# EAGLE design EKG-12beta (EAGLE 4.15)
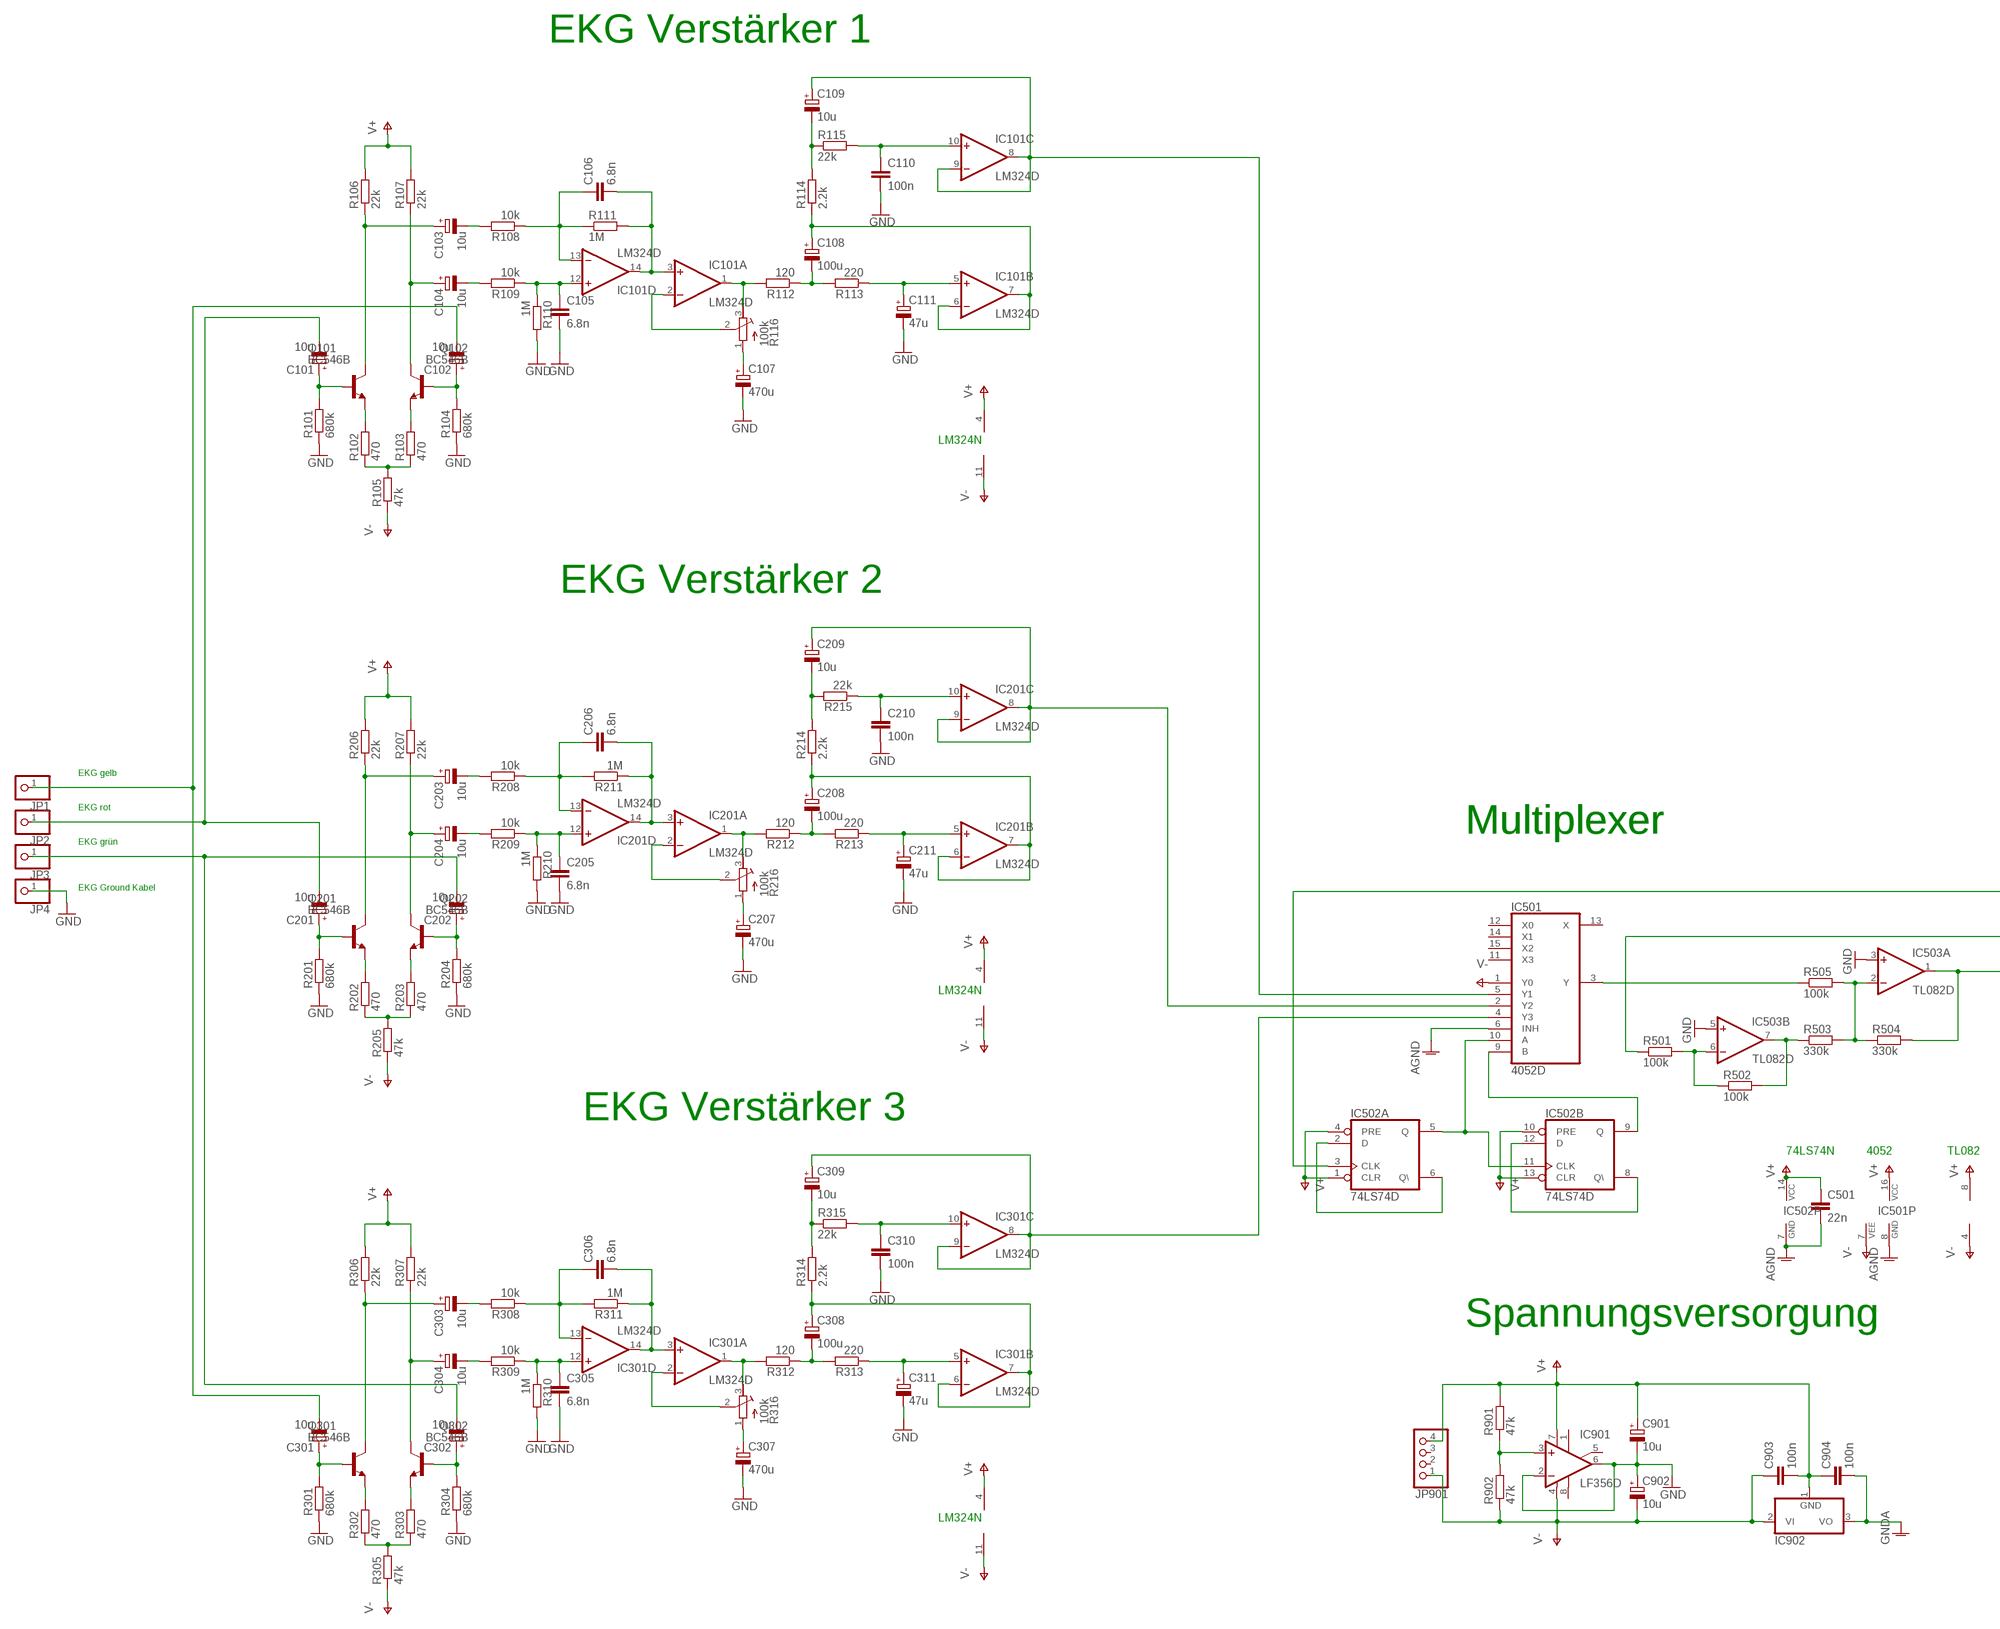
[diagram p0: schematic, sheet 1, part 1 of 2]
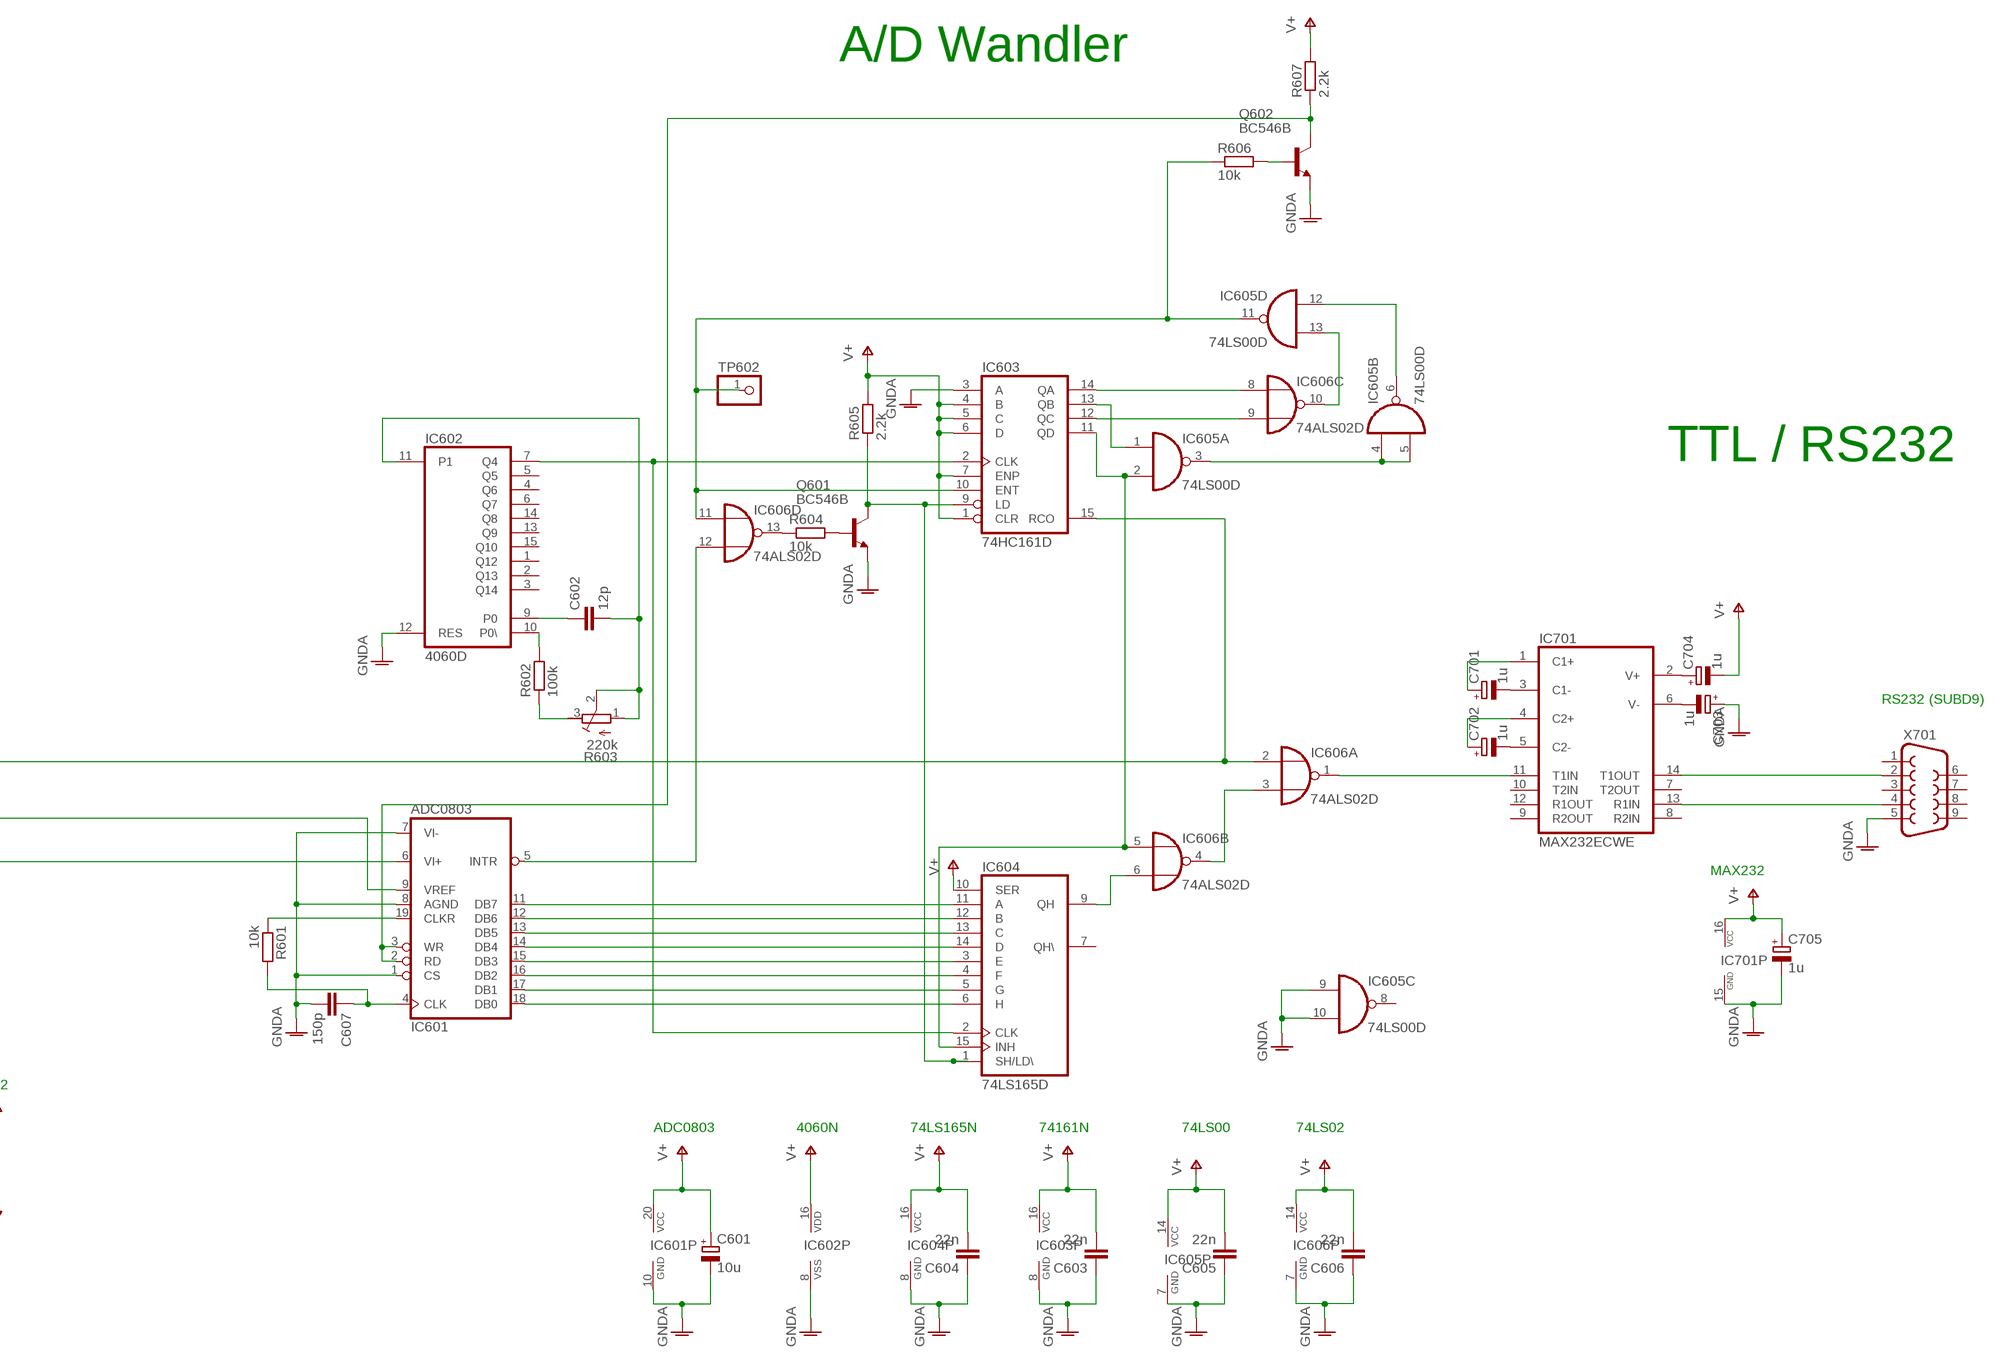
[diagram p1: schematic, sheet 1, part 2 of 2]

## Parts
C101  10u  CPOL-EUE2.5-5  [E2,5-5]
C102  10u  CPOL-EUE2.5-5  [E2,5-5]
C103  10u  CPOL-EUE2.5-5  [E2,5-5]
C104  10u  CPOL-EUE2.5-5  [E2,5-5]
C105  6.8n  C-EUC0805  [C0805]
C106  6.8n  C-EUC0805  [C0805]
C107  470u  CPOL-EUE5-10.5  [E5-10,5]
C108  100u  CPOL-EUE3.5-8  [E3,5-8]
C109  10u  CPOL-EUE2.5-5  [E2,5-5]
C110  100n  C-EUC0805  [C0805]
C111  47u  CPOL-EUE2.5-6  [E2,5-6]
C201  10u  CPOL-EUE2.5-6  [E2,5-6]
C202  10u  CPOL-EUE2.5-6  [E2,5-6]
C203  10u  CPOL-EUE2.5-6  [E2,5-6]
C204  10u  CPOL-EUE2.5-6  [E2,5-6]
C205  6.8n  C-EUC0805  [C0805]
C206  6.8n  C-EUC0805  [C0805]
C207  470u  CPOL-EUE5-10.5  [E5-10,5]
C208  100u  CPOL-EUE3.5-8  [E3,5-8]
C209  10u  CPOL-EUE2.5-6  [E2,5-6]
C210  100n  C-EUC0805  [C0805]
C211  47u  CPOL-EUE2.5-6  [E2,5-6]
C301  10u  CPOL-EUE2.5-6  [E2,5-6]
C302  10u  CPOL-EUE2.5-6  [E2,5-6]
C303  10u  CPOL-EUE2.5-6  [E2,5-6]
C304  10u  CPOL-EUE2.5-6  [E2,5-6]
C305  6.8n  C-EUC0805  [C0805]
C306  6.8n  C-EUC0805  [C0805]
C307  470u  CPOL-EUE5-10.5  [E5-10,5]
C308  100u  CPOL-EUE3.5-8  [E3,5-8]
C309  10u  CPOL-EUE2.5-6  [E2,5-6]
C310  100n  C-EUC0805  [C0805]
C311  47u  CPOL-EUE2.5-6  [E2,5-6]
C501  22n  C-EUC0805  [C0805]
C601  10u  CPOL-EUE2.5-6  [E2,5-6]
C602  12p  C-EUC0805  [C0805]
C603  22n  C-EUC0805  [C0805]
C604  22n  C-EUC0805  [C0805]
C605  22n  C-EUC0805  [C0805]
C606  22n  C-EUC0805  [C0805]
C607  150p  C-EUC0805  [C0805]
C701  1u  CPOL-EUCT3216  [CT3216]
C702  1u  CPOL-EUCT3216  [CT3216]
C703  1u  CPOL-EUCT3216  [CT3216]
C704  1u  CPOL-EUCT3216  [CT3216]
C705  1u  CPOL-EUCT3216  [CT3216]
C901  10u  CPOL-EUE2.5-6  [E2,5-6]
C902  10u  CPOL-EUE2.5-6  [E2,5-6]
C903  100n  C-EUC0805  [C0805]
C904  100n  C-EUC0805  [C0805]
IC101  LM324D  [SO14]
IC201  LM324D  [SO14]
IC301  LM324D  [SO14]
IC501  4052D  [SO16]
IC502  74LS74D  [SO14]
IC503  TL082D  [SO08]
IC601  ADC0803  ADC0801  [DIL20]
IC602  4060D  [SO16]
IC603  74HC161D  74HC160D  [SO16]
IC604  74LS165D  [SO16]
IC605  74LS00D  [SO14]
IC606  74ALS02D  [SO14]
IC701  MAX232ECWE  [SO16L]
IC901  LF356D  [SO08]
IC902  79L05Z  [TO92]
JP1  PINHD-1X1  [1X01]
JP2  PINHD-1X1  [1X01]
JP3  PINHD-1X1  [1X01]
JP4  PINHD-1X1  [1X01]
JP901  PINHD-1X4  [1X04]
Q101  BC546B  [TO92-EBC]
Q102  BC546B  [TO92-EBC]
Q201  BC546B  [TO92-EBC]
Q202  BC546B  [TO92-EBC]
Q301  BC546B  [TO92-EBC]
Q302  BC546B  [TO92-EBC]
Q601  BC546B  [TO92-EBC]
Q602  BC546B  [TO92-EBC]
R101  680k  R-EU_R0805  [R0805]
R102  470  R-EU_R0805  [R0805]
R103  470  R-EU_R0805  [R0805]
R104  680k  R-EU_R0805  [R0805]
R105  47k  R-EU_R0805  [R0805]
R106  22k  R-EU_R0805  [R0805]
R107  22k  R-EU_R0805  [R0805]
R108  10k  R-EU_R0805  [R0805]
R109  10k  R-EU_R0805  [R0805]
R110  1M  R-EU_R0805  [R0805]
R111  1M  R-EU_R0805  [R0805]
R112  120  R-EU_R0805  [R0805]
R113  220  R-EU_R0805  [R0805]
R114  2.2k  R-EU_R0805  [R0805]
R115  22k  R-EU_R0805  [R0805]
R116  100k  R-TRIMM64Y  [RTRIM64Y]
R201  680k  R-EU_R0805  [R0805]
R202  470  R-EU_R0805  [R0805]
R203  470  R-EU_R0805  [R0805]
R204  680k  R-EU_R0805  [R0805]
R205  47k  R-EU_R0805  [R0805]
R206  22k  R-EU_R0805  [R0805]
R207  22k  R-EU_R0805  [R0805]
R208  10k  R-EU_R0805  [R0805]
R209  10k  R-EU_R0805  [R0805]
R210  1M  R-EU_R0805  [R0805]
R211  1M  R-EU_R0805  [R0805]
R212  120  R-EU_R0805  [R0805]
R213  220  R-EU_R0805  [R0805]
R214  2.2k  R-EU_R0805  [R0805]
R215  22k  R-EU_R0805  [R0805]
R216  100k  R-TRIMM64Y  [RTRIM64Y]
R301  680k  R-EU_R0805  [R0805]
R302  470  R-EU_R0805  [R0805]
R303  470  R-EU_R0805  [R0805]
R304  680k  R-EU_R0805  [R0805]
R305  47k  R-EU_R0805  [R0805]
R306  22k  R-EU_R0805  [R0805]
R307  22k  R-EU_R0805  [R0805]
R308  10k  R-EU_R0805  [R0805]
R309  10k  R-EU_R0805  [R0805]
R310  1M  R-EU_R0805  [R0805]
R311  1M  R-EU_R0805  [R0805]
R312  120  R-EU_R0805  [R0805]
R313  220  R-EU_R0805  [R0805]
R314  2.2k  R-EU_R0805  [R0805]
R315  22k  R-EU_R0805  [R0805]
R316  100k  R-TRIMM64Y  [RTRIM64Y]
R501  100k  R-EU_R0805  [R0805]
R502  100k  R-EU_R0805  [R0805]
R503  330k  R-EU_R0805  [R0805]
R504  330k  R-EU_R0805  [R0805]
R505  100k  R-EU_R0805  [R0805]
R601  10k  R-EU_R0805  [R0805]
R602  100k  R-EU_R0805  [R0805]
R603  220k  R-TRIMM64Y  [RTRIM64Y]
R604  10k  R-EU_R0805  [R0805]
R605  2.2k  R-EU_R0805  [R0805]
R606  10k  R-EU_R0805  [R0805]
R607  2.2k  R-EU_R0805  [R0805]
R901  47k  R-EU_R0805  [R0805]
R902  47k  R-EU_R0805  [R0805]
TP602  PINHD-1X1  [1X01]
X701  F09H  [F09H]

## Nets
AGND: C501.2 IC501.6(INH) IC501.8(GND) IC502.7(P:GND)
GND: C105.2 C107.- C110.2 C111.- C205.2 C207.- C210.2 C211.- C305.2 C307.- C310.2 C311.- C901.- C902.+ IC503.3(A:+IN) IC503.5(B:+IN) IC901.2(-IN) IC901.6(OUT) JP4.1 R101.1 R104.1 R110.2 R201.1 R204.1 R210.2 R301.1 R304.1 R310.2
GNDA: C601.- C603.1 C604.1 C605.1 C606.1 C607.2 C703.+ C705.- C904.2 IC601.1(CS) IC601.7(VI-) IC601.8(AGND) IC601.10(GND) IC602.8(VSS) IC602.12(RES) IC603.3(A) IC603.8(GND) IC604.8(GND) IC605.7(P:GND) IC605.9(C:I0) IC605.10(C:I1) IC606.7(P:GND) IC701.15(GND) IC902.3(VO) Q601.E Q602.E X701.5
N$1: C104.+ Q102.C R107.1
N$2: C103.+ Q101.C R106.1
N$3: C103.- R108.2
N$4: C106.1 IC101.13(D:-IN) R108.1 R111.1
N$5: C104.- R109.2
N$6: C105.1 IC101.12(D:+IN) R109.1 R110.1
N$7: C102.+ Q102.B R104.2
N$8: C101.+ Q101.B R101.2
N$9: Q101.E R102.2
N$10: Q102.E R103.2
N$11: R102.1 R103.1 R105.2
N$12: C106.2 IC101.3(A:+IN) IC101.14(D:OUT) R111.2
N$13: C110.1 IC101.10(C:+IN) R115.2
N$14: IC101.2(A:-IN) R116.2(S)
N$15: IC101.1(A:OUT) R112.2 R116.3(A)
N$16: C107.+ R116.1(E)
N$17: C108.- R112.1 R113.2
N$18: C108.+ IC101.6(B:-IN) IC101.7(B:OUT) R114.1
N$19: C109.- R114.2 R115.1
N$20: C111.+ IC101.5(B:+IN) R113.1
N$21: C204.+ Q202.C R207.1
N$22: C101.- C201.- JP2.1
N$23: C109.+ IC101.8(C:OUT) IC101.9(C:-IN) IC501.5(Y1)
N$24: C303.- R308.2
N$25: C203.+ Q201.C R206.1
N$26: C304.- R309.2
N$27: C206.1 IC201.13(D:-IN) R208.1 R211.2
N$28: C203.- R208.2
N$29: C205.1 IC201.12(D:+IN) R209.1 R210.1
N$30: C202.+ Q202.B R204.2
N$31: C201.+ Q201.B R201.2
N$32: Q201.E R202.2
N$33: Q202.E R203.2
N$34: R202.1 R203.1 R205.2
N$35: C206.2 IC201.3(A:+IN) IC201.14(D:OUT) R211.1
N$36: IC201.2(A:-IN) R216.2(S)
N$37: IC201.1(A:OUT) R212.2 R216.3(A)
N$38: C207.+ R216.1(E)
N$39: C208.- R212.1 R213.2
N$40: C208.+ IC201.6(B:-IN) IC201.7(B:OUT) R214.1
N$41: C209.- R214.2 R215.2
N$42: C211.+ IC201.5(B:+IN) R213.1
N$43: C209.+ IC201.8(C:OUT) IC201.9(C:-IN) IC501.2(Y2)
N$44: C210.1 IC201.10(C:+IN) R215.1
N$45: C204.- R209.2
N$47: C304.+ Q302.C R307.1
N$48: C303.+ Q301.C R306.1
N$50: C306.1 IC301.13(D:-IN) R308.1 R311.2
N$52: C305.1 IC301.12(D:+IN) R309.1 R310.1
N$53: C302.+ Q302.B R304.2
N$54: C301.+ Q301.B R301.2
N$55: Q301.E R302.2
N$56: Q302.E R303.2
N$57: R302.1 R303.1 R305.2
N$58: C306.2 IC301.3(A:+IN) IC301.14(D:OUT) R311.1
N$59: IC301.2(A:-IN) R316.2(S)
N$60: IC301.1(A:OUT) R312.2 R316.3(A)
N$61: C307.+ R316.1(E)
N$62: C308.- R312.1 R313.2
N$63: C308.+ IC301.6(B:-IN) IC301.7(B:OUT) R314.1
N$64: C309.- R314.2 R315.1
N$65: C311.+ IC301.5(B:+IN) R313.1
N$66: C309.+ IC301.8(C:OUT) IC301.9(C:-IN) IC501.4(Y3)
N$67: C310.1 IC301.10(C:+IN) R315.2
N$68: C102.- C301.- JP1.1
N$69: C202.- C302.- JP3.1
N$70: IC501.3(Y) R505.1
N$71: IC503.2(A:-IN) R503.2 R504.1 R505.2
N$72: IC503.7(B:OUT) R502.2 R503.1
N$73: IC503.6(B:-IN) R501.2 R502.1
N$74: IC503.1(A:OUT) IC601.6(VI+) R504.2
N$75: IC501.10(A) IC502.5(A:Q) IC502.11(B:CLK)
N$76: IC501.9(B) IC502.9(B:Q)
N$77: IC502.2(A:D) IC502.6(A:Q\)
N$78: IC502.8(B:Q\) IC502.12(B:D)
N$79: IC602.10(P0\) R602.2
N$80: C602.1 IC602.9(P0)
N$81: IC901.3(+IN) R901.1 R902.2
N$82: C602.2 IC602.11(P1) R603.1(E) R603.2(S)
N$83: R602.1 R603.3(A)
N$84: IC602.7(Q4) IC603.2(CLK) IC604.2(CLK)
N$85: IC601.11(DB7) IC604.11(A)
N$86: IC601.12(DB6) IC604.12(B)
N$87: IC601.13(DB5) IC604.13(C)
N$88: IC601.14(DB4) IC604.14(D)
N$89: IC601.15(DB3) IC604.3(E)
N$90: IC601.16(DB2) IC604.4(F)
N$91: IC601.17(DB1) IC604.5(G)
N$92: IC601.18(DB0) IC604.6(H)
N$93: IC601.19(CLKR) R601.1
N$94: C607.1 IC601.4(CLK) R601.2
N$95: IC603.9(LD) IC604.1(SH/LD\) Q601.C R605.1
N$96: Q601.B R604.2
N$97: IC606.13(D:O) R604.1
N$98: IC601.5(INTR) IC606.12(D:I1)
N$99: IC606.1(A:O) IC701.11(T1IN)
N$100: IC603.10(ENT) IC605.11(D:O) IC606.11(D:I0) R606.1 TP602.1
N$101: Q602.B R606.2
N$102: IC603.11(QD) IC604.15(INH) IC605.2(A:I1) IC606.5(B:I0)
N$103: IC604.9(QH) IC606.6(B:I1)
N$104: IC502.3(A:CLK) IC603.15(RCO) IC606.2(A:I0)
N$105: IC606.3(A:I1) IC606.4(B:O)
N$106: IC603.13(QB) IC605.1(A:I0)
N$107: IC603.12(QC) IC606.9(C:I1)
N$108: IC603.14(QA) IC606.8(C:I0)
N$109: IC605.3(A:O) IC605.4(B:I0) IC605.5(B:I1)
N$110: IC605.6(B:O) IC605.12(D:I0)
N$111: IC605.13(D:I1) IC606.10(C:O)
N$112: IC601.2(RD) IC601.3(WR) Q602.C R607.1
N$113: IC701.14(T1OUT) X701.2
N$114: C702.- IC701.5(C2-)
N$115: C701.- IC701.3(C1-)
N$116: C702.+ IC701.4(C2+)
N$117: C701.+ IC701.1(C1+)
N$118: C703.- IC701.6(V-)
N$119: C704.+ IC701.2(V+)
N$120: IC701.13(R1IN) X701.4
N$128: IC601.9(VREF) R501.1
V+: C501.1 C601.+ C603.2 C604.2 C605.2 C606.2 C704.- C705.+ C901.+ C903.2 C904.1 IC101.4(P:V+) IC201.4(P:V+) IC301.4(P:V+) IC501.16(VCC) IC502.1(A:CLR) IC502.4(A:PRE) IC502.10(B:PRE) IC502.13(B:CLR) IC502.14(P:VCC) IC503.8(P:V+) IC601.20(VCC) IC602.16(VDD) IC603.1(CLR) IC603.4(B) IC603.5(C) IC603.6(D) IC603.7(ENP) IC603.16(VCC) IC604.10(SER) IC604.16(VCC) IC605.14(P:VCC) IC606.14(P:VCC) IC701.16(VCC) IC901.7(V+) IC902.1(GND) JP901.4 R106.2 R107.2 R206.2 R207.2 R306.2 R307.2 R605.2 R607.2 R901.2
V-: C902.- C903.1 IC101.11(P:V-) IC201.11(P:V-) IC301.11(P:V-) IC501.1(Y0) IC501.7(VEE) IC503.4(P:V-) IC901.4(V-) IC902.2(VI) JP901.1 R105.1 R205.1 R305.1 R902.1
Unconnected: IC501.11(X3) IC501.12(X0) IC501.13(X) IC501.14(X1) IC501.15(X2) IC602.1(Q12) IC602.2(Q13) IC602.3(Q14) IC602.4(Q6) IC602.5(Q5) IC602.6(Q7) IC602.13(Q9) IC602.14(Q8) IC602.15(Q10) IC604.7(QH\) IC605.8(C:O) IC701.7(T2OUT) IC701.8(R2IN) IC701.9(R2OUT) IC701.10(T2IN) IC701.12(R1OUT) IC901.1(ON1) IC901.5(ON2) IC901.8(OPT) JP901.2 JP901.3 X701.1 X701.3 X701.6 X701.7 X701.8 X701.9

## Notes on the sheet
- EKG Verstärker 1
- A/D Wandler
- LM324N
- EKG Verstärker 2
- TTL / RS232
- EKG gelb
- EKG rot
- Multiplexer | Multiplexer
- EKG grün | RS232 (SUBD9)
- EKG Ground Kabel
- MAX232
- LM324N
- EKG Verstärker 3
- 74LS74N | 4052 | TL082
- ADC0803 | 4060N | 74LS165N | 74161N | 74LS00 | 74LS02
- Spannungsversorgung
- LM324N

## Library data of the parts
C101-C104 C107-C109 C111 C201-C204 C207-C209 C211 C301-C304 C307-C309 C311 C601 C701-C705 C901 C902 = rcl:CPOL-EU: POLARIZED CAPACITOR, European symbol
C105 C106 C110 C205 C206 C210 C305 C306 C310 C501 C602-C607 C903 C904 = rcl:C-EU: CAPACITOR, European symbol
IC101 IC201 IC301 = linear:LM324: OP AMP
IC501 = 40xx:4052: Dual 4-channel ANALOG MULTIPLEXER
IC502 = 74xx-eu:74*74: Dual D type positive edge triggered FLIP FLOP, preset and clear
IC503 = linear:TL082: OP AMP
IC601 = linear:ADC0801: 8-bit A/D CONVERTER
IC602 = 40xx:4060: 14-stage binary/ripple COUNTER
IC603 = 74xx-eu:74*160: Synchronous 4-bit COUNTER
IC604 = 74xx-eu:74*165: 8-bit parallel load SHIFT REGISTER
IC605 = 74xx-eu:74*00: Quad 2-input NAND gate
IC606 = 74xx-eu:74*02: Quad 2-input NOR gate
IC701 = maxim:MAX232ECWE: RS232 TRANSEIVER
IC901 = linear:LF356: OP AMP
IC902 = linear:79*: Negative VOLTAGE REGULATOR
JP1-JP4 TP602 = pinhead:PINHD-1X1: PIN HEADER
JP901 = pinhead:PINHD-1X4: PIN HEADER
Q101 Q102 Q201 Q202 Q301 Q302 Q601 Q602 = transistor-npn:BC546*: NPN Transistor
R101-R115 R201-R215 R301-R315 R501-R505 R601 R602 R604-R607 R901 R902 = rcl:R-EU_: RESISTOR, European symbol
R116 R216 R316 R603 = rcl:R-TRIMM: Trimm resistor
X701 = con-subd:F09: SUB-D

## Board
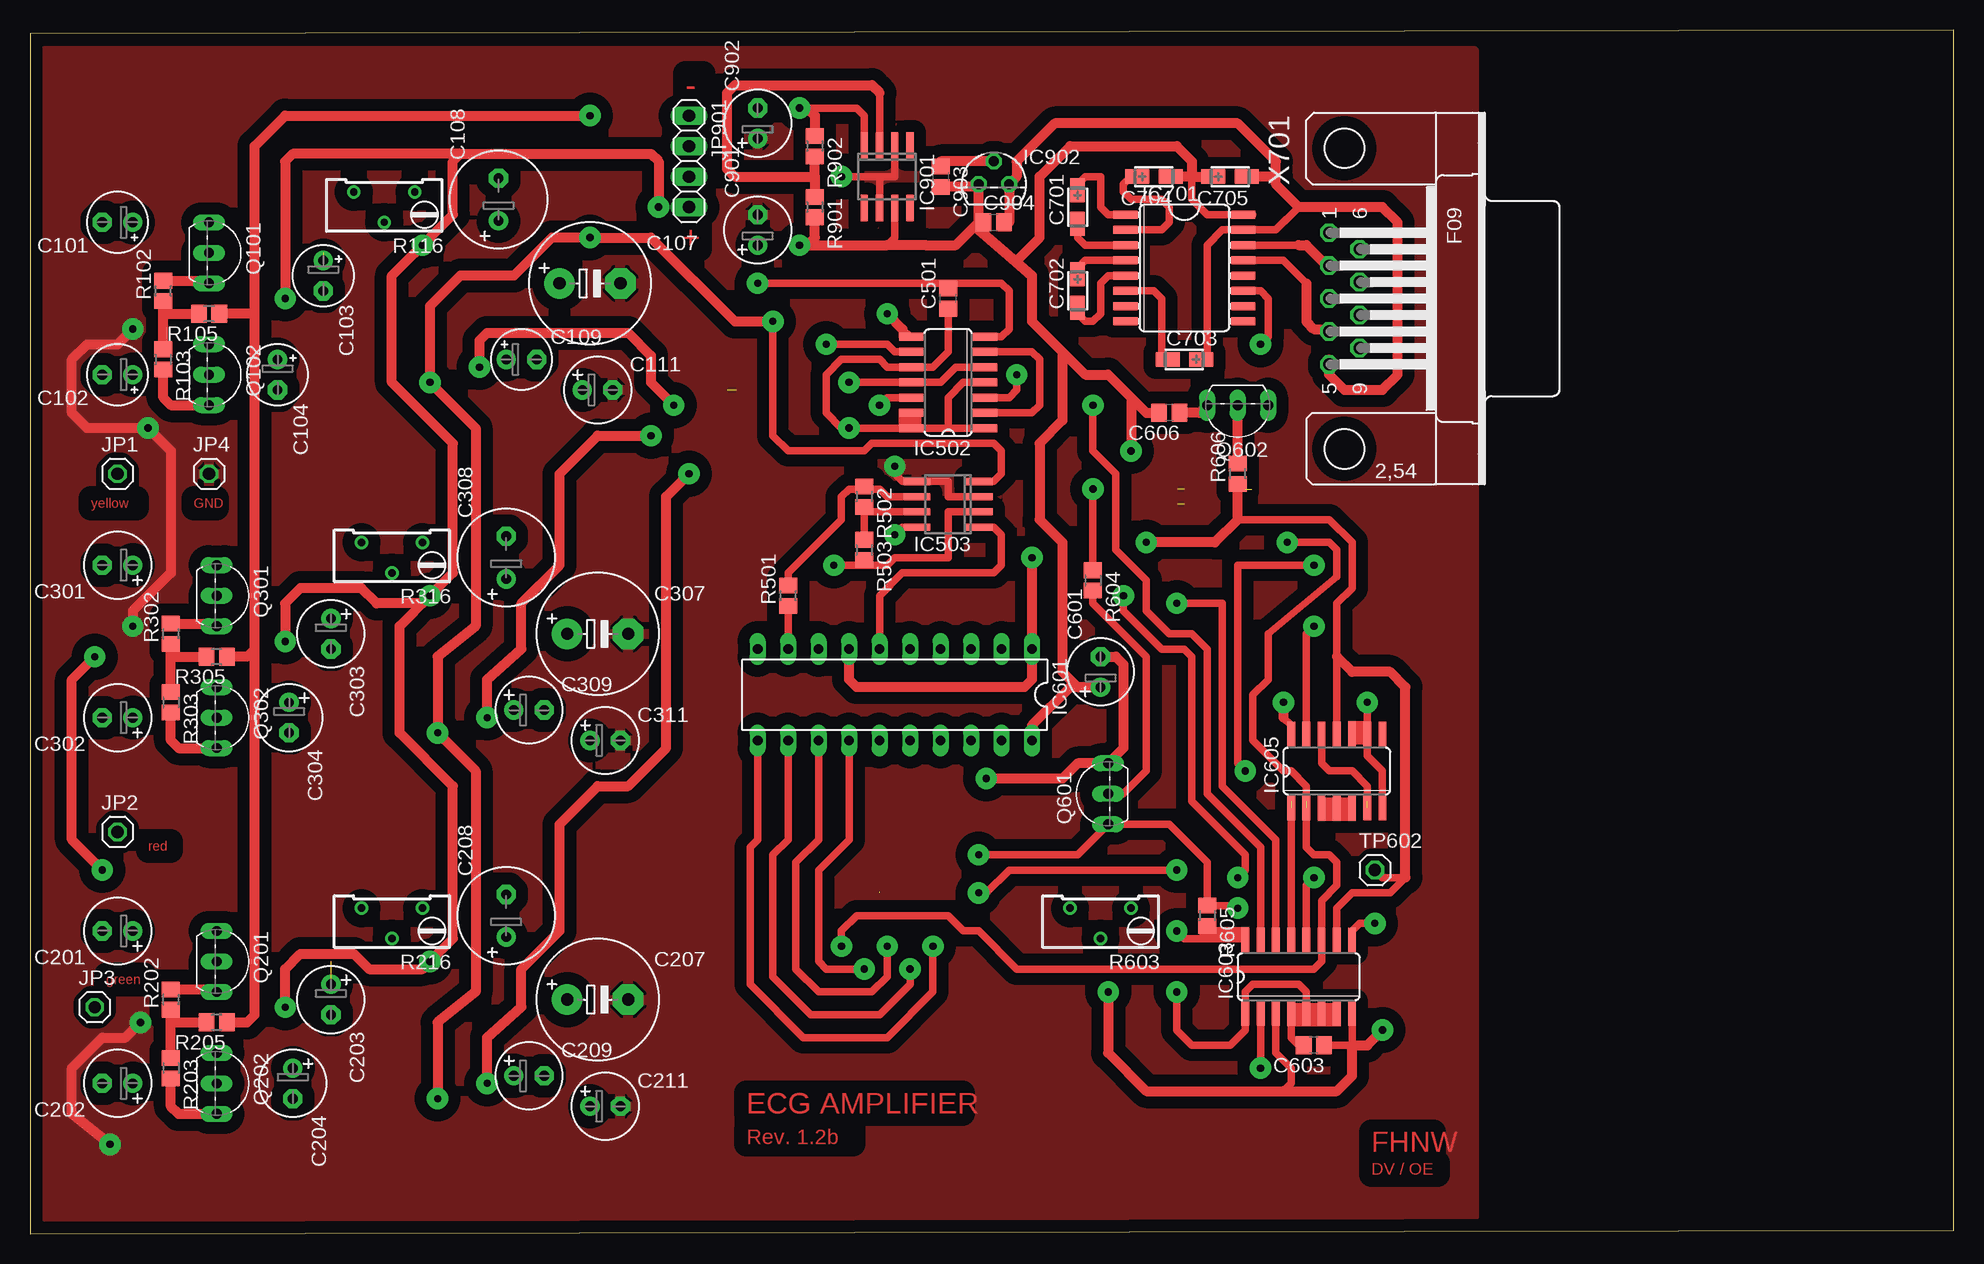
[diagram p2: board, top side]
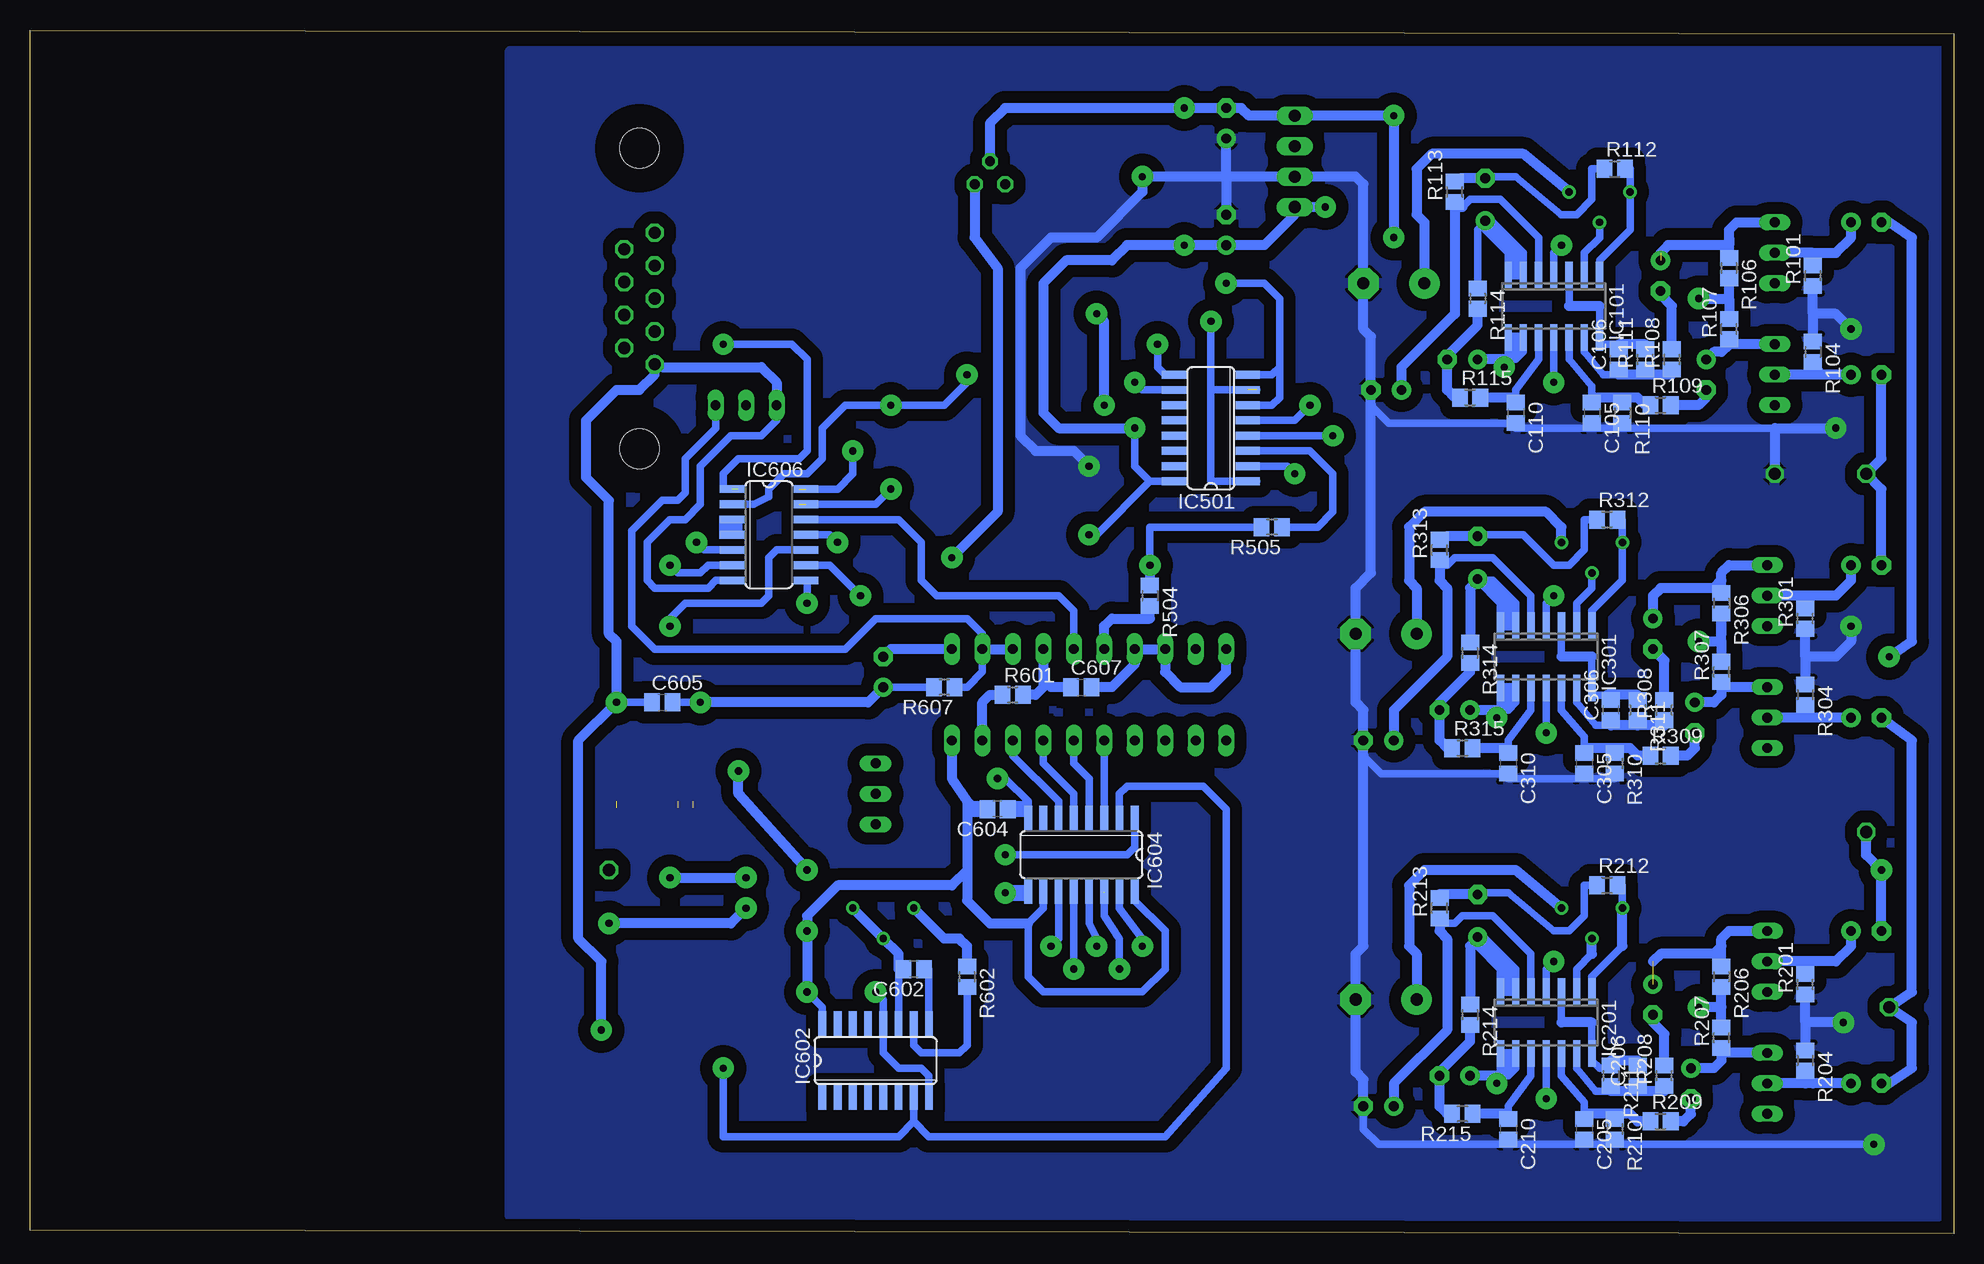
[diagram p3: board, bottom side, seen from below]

Size 160.32 x 100.32 mm. Coordinates in mm from the lower left corner, seen from the top.
Outline: 0,0 160.32,0.32 160.32,100.32 0,100 0,0
Copper layers (1*16): Top 0.035mm / dielectric 1.5mm / Bottom 0.035mm
Design rules "default": minimum track width 10mil, minimum drill 24mil, track to track 8mil, track to pad 8mil, pad to pad 8mil, via to via 8mil, smd to smd 8mil, copper to edge 40mil, drill to drill 8mil, minimum pad ring 10mil, minimum via ring 8mil, stop-mask expansion 4mil, vias tented up to drill 0mil, thermal gap 10mil

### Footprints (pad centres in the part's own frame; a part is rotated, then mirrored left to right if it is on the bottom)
E2,5-5 = drill 0.813 pad 1.6 round: + -1.27,0 | drill 0.813 pad 1.6 octagon: - 1.27,0
C0805 = smd 1.3 x 1.5: 1 -0.85,0; 2 0.85,0
E5-10,5 = drill 1.016 pad 2.54 round: + -2.54,0 | drill 1.016 pad 2.54 octagon: - 2.54,0
E3,5-8 = drill 0.813 pad 1.6 round: + -1.778,0 | drill 0.813 pad 1.6 octagon: - 1.778,0
E2,5-6 = drill 0.813 pad 1.6 round: + -1.27,0 | drill 0.813 pad 1.6 octagon: - 1.27,0
CT3216 = smd 2 x 1.2: + 1.4,0; - -1.4,0
SO14 = smd 0.6 x 2.2: 1 -3.81,-2.6; 2 -2.54,-2.6; 3 -1.27,-2.6; 4 0,-2.6; 5 1.27,-2.6; 6 2.54,-2.6; 7 3.81,-2.6; 8 3.81,2.6; 9 2.54,2.6; 10 1.27,2.6; 11 0,2.6; 12 -1.27,2.6; 13 -2.54,2.6; 14 -3.81,2.6
SO16 = smd 0.66 x 2.032: 1 -4.445,-3.073; 2 -3.175,-3.073; 3 -1.905,-3.073; 4 -0.635,-3.073; 5 0.635,-3.073; 6 1.905,-3.073; 7 3.175,-3.073; 8 4.445,-3.073; 9 4.445,3.073; 10 3.175,3.073; 11 1.905,3.073; 12 0.635,3.073; 13 -0.635,3.073; 14 -1.905,3.073; 15 -3.175,3.073; 16 -4.445,3.073
SO14' = smd 0.66 x 2.032: 1 -3.81,-3.073; 2 -2.54,-3.073; 3 -1.27,-3.073; 4 0,-3.073; 5 1.27,-3.073; 6 2.54,-3.073; 7 3.81,-3.073; 8 3.81,3.073; 9 2.54,3.073; 10 1.27,3.073; 11 0,3.073; 12 -1.27,3.073; 13 -2.54,3.073; 14 -3.81,3.073
SO08 = smd 0.6 x 2.2: 1 -1.905,-2.6; 2 -0.635,-2.6; 3 0.635,-2.6; 4 1.905,-2.6; 5 1.905,2.6; 6 0.635,2.6; 7 -0.635,2.6; 8 -1.905,2.6
DIL20 = drill 0.813 long: 1 -11.43,-3.81; 2 -8.89,-3.81; 3 -6.35,-3.81; 4 -3.81,-3.81; 5 -1.27,-3.81; 6 1.27,-3.81; 7 3.81,-3.81; 8 6.35,-3.81; 9 8.89,-3.81; 10 11.43,-3.81; 11 11.43,3.81; 12 8.89,3.81; 13 6.35,3.81; 14 3.81,3.81; 15 1.27,3.81; 16 -1.27,3.81; 17 -3.81,3.81; 18 -6.35,3.81; 19 -8.89,3.81; 20 -11.43,3.81
SO16L = smd 0.66 x 2.032: 1 -4.445,-4.902; 2 -3.175,-4.902; 3 -1.905,-4.902; 4 -0.635,-4.902; 5 0.635,-4.902; 6 1.905,-4.902; 7 3.175,-4.902; 8 4.445,-4.902; 9 4.445,4.902; 10 3.175,4.902; 11 1.905,4.902; 12 0.635,4.902; 13 -0.635,4.902; 14 -1.905,4.902; 15 -3.175,4.902; 16 -4.445,4.902
TO92 = drill 0.813 octagon: 1 -1.27,0; 2 0,1.905; 3 1.27,0
1X01 = drill 1.016 octagon: 1 0,0
1X04 = drill 1.016 long: 1 -3.81,0; 2 -1.27,0; 3 1.27,0; 4 3.81,0
TO92-EBC = drill 0.813 long: B 0,-1.27; C -2.54,-1.27; E 2.54,-1.27
R0805 = smd 1.3 x 1.5: 1 -0.85,0; 2 0.85,0
RTRIM64Y = drill 0.61 round: 1 0,-2.54; 2 -2.54,0; 3 0,2.54
F09H = drill 1.016 octagon: 1 -5.486,-1.27; 2 -2.743,-1.27; 3 0,-1.27; 4 2.743,-1.27; 5 5.486,-1.27; 6 -4.115,1.27; 7 -1.372,1.27; 8 1.372,1.27; 9 4.115,1.27 | hole 3.302: -12.522,0; 12.522,0

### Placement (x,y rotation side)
C101  7.3,84.29 180 top
C102  7.3,71.59 180 top
C103  24.44,79.84 270 top
C104  20.63,71.59 270 top
C105  30.16,68.41 270 bottom
C106  27.93,72.86 90 bottom
C107  46.67,79.21 0 top
C108  39.05,86.19 90 top
C109  40.95,72.86 0 top
C110  36.51,68.41 270 bottom
C111  47.3,70.32 0 top
C201  7.3,25.23 180 top
C202  7.3,12.54 180 top
C203  25.08,19.52 270 top
C204  21.9,12.54 270 top
C205  30.79,8.73 270 bottom
C206  26.35,13.17 90 bottom
C207  47.3,19.52 0 top
C208  39.68,26.5 90 top
C209  41.59,13.17 0 top
C210  37.14,8.73 270 bottom
C211  47.94,10.63 0 top
C301  7.3,55.71 180 top
C302  7.3,43.02 180 top
C303  25.08,50 270 top
C304  21.59,43.02 270 top
C305  30.79,39.2 270 bottom
C306  28.57,43.65 90 bottom
C307  47.3,50 0 top
C308  39.68,56.35 90 top
C309  41.59,43.65 0 top
C310  37.14,39.2 270 bottom
C311  47.94,41.11 0 top
C501  76.51,77.94 90 top
C601  89.21,46.82 90 top
C602  86.67,22.06 180 bottom
C603  106.99,15.71 180 top
C604  79.69,35.39 180 bottom
C605  107.63,44.28 0 bottom
C606  94.93,68.41 180 top
C607  72.7,45.55 0 bottom
C701  87.31,85.56 90 top
C702  87.31,78.58 90 top
C703  96.2,72.86 0 top
C704  93.66,88.1 180 top
C705  100.01,88.1 180 top
C901  60.64,83.66 90 top
C902  60.64,92.55 90 top
C903  75.88,88.1 270 top
C904  80.32,84.29 0 top
IC101  33.33,77.3 180 bottom
IC201  33.97,17.61 180 bottom
IC301  33.97,48.09 180 bottom
IC501  61.91,67.14 90 bottom
IC502  74LS74D  [SO14']  76.51,70.95 90 top
IC503  76.51,60.8 90 top
IC601  72.07,44.92 180 top
IC602  89.85,14.44 0 bottom
IC603  105.72,21.42 0 top
IC604  72.7,31.58 180 bottom
IC605  74LS00D  [SO14']  108.9,38.57 0 top
IC606  74ALS02D  [SO14']  98.74,58.25 270 bottom
IC701  96.2,80.48 270 top
IC901  71.43,88.1 180 top
IC902  80.32,87.47 0 top
JP1  7.3,63.34 0 top
JP2  7.3,33.49 0 top
JP3  5.39,18.88 0 top
JP4  14.92,63.34 0 top
JP901  54.92,89.37 270 top
Q101  16.19,81.75 270 top
Q102  16.19,71.59 270 top
Q201  16.82,22.7 270 top
Q202  16.82,12.54 270 top
Q301  16.82,53.17 270 top
Q302  16.82,43.02 270 top
Q601  88.58,36.66 90 top
Q602  100.64,67.78 180 top
R101  11.74,79.84 90 bottom
R102  11.11,78.58 90 top
R103  11.11,72.86 270 top
R104  11.74,73.5 270 bottom
R105  14.92,76.67 180 top
R106  18.73,80.48 270 bottom
R107  18.73,75.4 90 bottom
R108  23.49,72.86 90 bottom
R109  24.44,69.05 0 bottom
R110  27.62,68.41 270 bottom
R111  25.71,72.86 90 bottom
R112  28.25,88.73 0 bottom
R113  41.59,86.83 90 bottom
R114  39.68,77.94 270 bottom
R115  40.32,69.69 0 bottom
R116  29.52,86.83 90 top
R201  12.38,20.79 90 bottom
R202  11.74,19.52 90 top
R203  11.74,13.81 270 top
R204  12.38,14.44 270 bottom
R205  15.55,17.61 180 top
R206  19.36,21.42 270 bottom
R207  19.36,16.34 90 bottom
R208  24.12,13.17 90 bottom
R209  24.44,9.36 0 bottom
R210  28.25,8.73 270 bottom
R211  28.57,13.17 270 bottom
R212  28.89,29.04 0 bottom
R213  42.86,27.14 90 bottom
R214  40.32,18.25 270 bottom
R215  40.95,10 180 bottom
R216  30.16,27.14 90 top
R301  12.38,51.27 90 bottom
R302  11.74,50 90 top
R303  11.74,44.28 270 top
R304  12.38,44.92 270 bottom
R305  15.55,48.09 180 top
R306  19.36,52.54 270 bottom
R307  19.36,46.82 90 bottom
R308  24.12,43.65 90 bottom
R309  24.44,39.84 0 bottom
R310  28.25,39.2 270 bottom
R311  26.35,43.65 270 bottom
R312  28.89,59.52 0 bottom
R313  42.86,56.98 90 bottom
R314  40.32,48.41 270 bottom
R315  40.95,40.48 0 bottom
R316  30.16,57.62 90 top
R501  63.18,53.17 90 top
R502  69.53,61.43 270 top
R503  69.53,56.98 270 top
R504  66.99,53.17 270 bottom
R505  56.83,58.89 180 bottom
R601  78.42,44.92 0 bottom
R602  82.23,21.42 270 bottom
R603  89.21,27.14 90 top
R604  88.58,54.45 270 top
R605  98.1,26.5 270 top
R606  100.64,63.34 90 top
R607  84.13,45.55 180 bottom
R901  65.4,85.56 270 top
R902  65.4,90.64 270 top
TP602  112.07,30.31 0 top
X701  109.53,77.94 270 top

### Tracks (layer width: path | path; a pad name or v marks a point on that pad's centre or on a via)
AGND  (via drill 0.6 pad 1.78)
  Top 0.61: IC502.7 80.96,74.77 81.59,75.4 81.59,78.58 80.96,79.21 76.51,79.21 | 76.51,79.21 C501.2 | v60.64,79.21 76.51,79.21
  Bottom 0.61: IC501.6 56.83,69.05 56.19,69.69 56.19,72.22 | v60.64,79.21 57.46,79.21 56.19,77.94 56.19,72.22 | IC501.8 56.83,71.59 56.19,72.22
GND  (via drill 0.6 pad 1.78)
  Top 0.61: v67.62,88.1 70.8,88.1 | 70.8,88.1 IC901.6 | 70.8,88.1 72.07,88.1 IC901.2 | IC503.3 76.51,61.43 76.51,62.7 IC503.5 72.7,62.7 72.07,63.34 v72.07,63.97
  Top 0.813: v8.57,75.4 7.3,74.13 4.76,74.13 3.49,72.86 3.49,68.41 4.76,67.14 v9.84,67.14 11.74,65.24 11.74,55.08 8.57,51.91 v8.57,50.63 | v6.66,7.46 3.49,10 3.49,13.81 6.03,16.34 7.93,16.34 v9.2,17.61
  Bottom 0.61: 28.25,38.57 R310.2 28.25,37.94 30.79,37.94 | 28.25,7.46 30.79,7.46 | 30.16,67.14 27.62,67.14 | 30.79,7.46 C205.2 | 30.79,7.46 37.14,7.46 | 37.14,7.46 C210.2 | 37.14,7.46 47.94,7.46 49.21,8.73 C211.- | 30.79,37.94 C305.2 | 30.79,37.94 37.14,37.94 C310.2 47.72,38.35 49.21,39.84 | 30.16,67.14 C105.2 | 30.16,67.14 36.51,67.14 C110.2 47.09,67.56 48.57,69.05 | 27.62,67.14 R110.2 | 27.62,67.14 14.92,67.14 | 28.25,7.46 R210.2 | v6.66,7.46 28.25,7.46
  Bottom 0.813: 12.38,48.09 R304.1 | 12.38,20.15 R201.1 12.38,17.61 | 11.74,79.21 R101.1 11.74,76.67 | C211.- 49.21,12.85 49.84,13.49 C207.- 49.84,23.33 49.21,23.96 49.21,39.84 C311.- 49.21,43.65 49.84,44.28 C307.- 49.84,53.81 48.57,55.08 48.57,69.05 C111.- 48.57,74.77 49.21,75.4 C107.- 49.21,87.47 49.84,88.1 60.64,88.1 | 60.64,88.1 C902.+ | 60.64,88.1 C901.- | 60.64,88.1 v67.62,88.1 67.62,86.83 71.43,83.02 75.24,83.02 77.78,80.48 77.78,66.51 76.51,65.24 73.34,65.24 v72.07,63.97 | 11.74,76.67 R104.1 | 11.74,76.67 9.84,76.67 v8.57,75.4 | v9.84,67.14 14.92,67.14 JP4.1 | 12.38,48.09 R301.1 | 12.38,48.09 9.84,48.09 8.57,49.37 v8.57,50.63 | 12.38,17.61 R204.1 | v9.2,17.61 12.38,17.61
  pour Bottom (isolate 1.016): 0.95,98.58 0.95,1.74 1.27,1.42 120.33,1.42 120.33,98.58
  pour Top (isolate 1.016): 1.27,98.58 120.33,98.58 120.33,1.42 1.27,1.42
GNDA  (via drill 0.6 pad 1.78)
  Top 0.61: 68.26,47.46 IC601.7 | 103.82,83.66 105.09,84.92 | C703.+ 98.1,72.86 98.1,82.39 99.37,83.66 IC701.15 103.82,83.66 | 110.17,15.71 110.17,15.08 | IC605.10 110.17,41.74 110.27,41.64 IC605.9 | IC603.3 103.82,15.08 105.09,13.81 105.09,12.54 104.45,11.9 | 110.17,15.71 C603.1 | v111.44,44.28 IC605.9 | IC605.9 111.44,39.84 112.71,38.57 IC605.7 112.71,35.39 | 110.17,15.71 IC603.8 | 105.72,85.56 103.82,83.66
  Top 0.813: 108.26,72.86 X701.5 108.26,71.59 109.53,70.32 112.71,70.32 113.98,71.59 113.98,84.29 112.71,85.56 105.72,85.56 103.82,87.47 103.82,88.1 | v83.5,56.35 IC601.1 83.5,46.19 82.86,45.55 68.89,45.55 68.26,46.19 68.26,47.46 | C606.1 97.47,68.41 Q602.E | C601.- 90.48,48.09 91.12,47.46 91.12,40.48 Q601.E 87.31,39.2 86.04,37.94 v79.69,37.94 | v89.85,20.15 89.85,15.08 93.02,11.9 104.45,11.9 108.9,11.9 110.17,13.17 110.17,15.71 111.44,15.71 v112.71,16.98 | C904.2 81.59,84.29 IC902.3 82.23,88.1 82.23,89.37 85.4,92.55 100.64,92.55 103.82,89.37 103.82,88.1 | 103.82,88.1 C705.-
  Bottom 0.61: C607.2 72.07,45.55 | IC602.8 85.4,13.17 86.04,13.81 87.94,13.81 89.21,15.08 IC602.12 89.21,19.52 v89.85,20.15 | IC606.7 103.18,54.45 103.82,53.81 108.26,53.81 108.9,54.45 108.9,57.62 106.99,59.52 105.72,59.52 104.45,60.8 104.45,63.97 101.91,66.51 99.37,66.51 98.1,67.78 Q602.E | 77.15,35.39 IC604.8 | 77.15,35.39 C604.1 | 77.15,35.39 77.15,36.03 79.05,37.94 v79.69,37.94 | v111.44,44.28 C605.1 v111.44,44.28
  Bottom 0.813: C607.2 70.16,45.55 68.26,47.46 IC601.7 IC601.8 65.72,46.82 64.45,45.55 61.91,45.55 60.64,46.82 IC601.10 | C601.- 88.58,48.73 IC601.1 | IC902.3 81.59,83.02 79.69,80.48 79.69,60.16 v83.5,56.35 | Q602.E 98.1,70.95 99.37,72.22 107.63,72.22 108.26,72.86 X701.5 108.26,71.59 109.53,70.32 111.44,70.32 113.98,67.78 113.98,63.02 112.07,61.11 112.07,50 111.44,49.37 v111.44,44.28 114.61,41.11 114.61,24.6 112.71,22.7 v112.71,16.98
N$1
  Bottom 0.813: Q102.C 18.73,74.13 | 18.73,74.13 19.36,73.5 20,73.5 C104.+ | 18.73,74.13 R107.1
N$2  (1 unrouted)
  Bottom 0.813: 24.44,81.75 23.81,82.39 18.73,82.39 18.73,83.02 | Q101.C 18.09,84.29 18.73,83.66 18.73,83.02 | R106.1 18.73,83.02
N$3
  Bottom 0.813: C103.- 24.44,78.26 23.49,77.3 R108.2
N$4
  Bottom 0.61: IC101.13 30.79,73.5 29.2,71.59 27.93,71.59
  Bottom 0.813: R108.1 23.49,71.59 25.71,71.59 | 25.71,71.59 R111.1 | C106.1 27.93,71.59 25.71,71.59
N$5
  Bottom 0.813: C104.- 20.63,69.69 21.27,69.05 R109.2
N$6
  Bottom 0.61: IC101.12 32.06,72.86 30.16,70.64 30.16,69.69
  Bottom 0.813: C105.1 30.16,69.69 27.62,69.69 | 27.62,69.69 R110.1 | 27.62,69.69 26.35,69.69 25.71,69.05 R109.1
N$7
  Bottom 0.813: C102.+ 11.11,71.59 | 11.74,72.86 R104.2 11.11,71.59 | 11.11,71.59 Q102.B
N$8
  Bottom 0.813: 11.74,80.48 R101.2 11.74,81.75 | C101.+ 8.57,83.02 9.84,81.75 11.74,81.75 | 11.74,81.75 Q101.B
N$9
  Top 0.813: R102.2 14.7,79.42 Q101.E
N$10
  Top 0.813: Q102.E 11.74,69.05 11.11,69.69 R103.2
N$11
  Top 0.813: R103.1 11.11,76.67 | 11.11,76.67 R102.1 | 11.11,76.67 R105.2
N$12
  Bottom 0.61: 27.93,74.13 29.52,74.13 IC101.14 29.52,77.3 | 32.06,77.3 IC101.3
  Bottom 0.813: R111.2 25.71,74.13 27.93,74.13 C106.2 | 29.52,77.3 32.06,77.3
N$13
  Bottom 0.61: IC101.10 34.6,72.86 36.51,70.32 36.51,69.69 C110.1
  Bottom 0.813: 36.51,69.69 R115.2
N$14
  Bottom 0.61: IC101.2 30.79,81.75 29.52,83.02 R116.2
N$15
  Bottom 0.61: IC101.1 29.52,81.11 26.98,83.66 R116.3 26.98,88.73 R112.2
N$16
  Bottom 0.813: R116.1 35.87,90 43.49,90 44.76,88.73 44.76,84.92 44.13,84.29 C107.+
N$17
  Bottom 0.61: R112.1 30.16,88.73 30.16,86.19 31.43,84.92 32.7,84.92 36.51,88.1 38.41,88.1 39.05,87.47 C108.-
  Bottom 0.813: R113.2 41.59,87.47 41.08,87.97 C108.-
N$18
  Bottom 0.61: IC101.6 35.87,81.75 38.41,84.29 39.05,84.29 | IC101.7 37.14,81.75 39.05,83.66 39.05,84.29 | 39.05,84.29 C108.+ | R114.1 39.68,83.66 39.05,84.29
N$19
  Bottom 0.61: R115.1 41.59,69.69
  Bottom 0.813: 41.59,69.69 42.22,70.32 C109.- 42.22,73.18 39.68,75.72 R114.2
N$20
  Bottom 0.61: IC101.5 34.6,83.02 37.78,86.19 40.32,86.19 40.95,85.56
  Bottom 0.813: C111.+ 46.03,72.22 41.59,76.67 41.59,85.56 | 41.59,85.56 R113.1 | 40.95,85.56 41.59,85.56
N$21
  Bottom 0.813: Q202.C 19.36,15.08 R207.1 | R207.1 19.36,15.71 | R207.1 19.36,14.44 20,13.81 C204.+
N$22  (via drill 0.6 pad 1.78)
  Top 0.813: v5.39,48.09 3.49,46.19 3.49,32.85 v6.03,30.31
  Bottom 0.813: C101.- 5.39,84.29 3.49,83.02 3.49,49.37 v5.39,48.09 | C201.- v6.03,30.31 7.3,31.58 JP2.1
N$23  (via drill 0.6 pad 1.78)
  Top 0.813: v37.46,72.22 37.46,74.45 38.09,75.08 49.84,75.08 51.75,73.18 51.75,70.95 v53.65,69.05
  Bottom 0.61: IC101.9 35.87,73.5 36.51,72.86 37.14,72.86 | 37.14,72.86 IC101.8 | 37.46,72.86 37.14,72.86 | IC501.5 54.92,67.78 v53.65,69.05
  Bottom 0.813: C109.+ 37.46,72.86 v37.46,72.22
N$24
  Bottom 0.813: C303.- 24.13,47.78 R308.2
N$25  (1 unrouted)
  Bottom 0.813: 19.36,23.96 20,23.33 24.44,23.33 25.08,22.7 | R206.1 19.36,23.96 | Q201.C 18.73,25.23 19.36,24.6 19.36,23.96
N$26
  Bottom 0.813: C304.- 21.59,40.48 22.22,39.84 R309.2
N$27
  Bottom 0.61: IC201.13 31.43,13.81 29.84,11.9 28.57,11.9
  Bottom 0.813: R208.1 24.13,11.9 26.35,11.9 | 26.35,11.9 C206.1 | R211.2 28.57,11.9 26.35,11.9
N$28
  Bottom 0.813: C203.- 25.08,17.61 24.13,16.66 R208.2
N$29
  Bottom 0.61: IC201.12 32.7,13.17 30.79,10.95 C205.1 30.79,9.36
  Bottom 0.813: 25.08,9.36 25.29,9.58 | C205.1 30.79,10 28.25,10 | 28.25,10 R210.1 | 28.25,10 26.98,10 26.35,9.36 25.08,9.36 | R209.1 25.08,9.36
N$30
  Bottom 0.813: C202.+ 11.74,12.54 | 11.74,12.54 12.38,12.54 R204.2 | 11.74,12.54 Q202.B
N$31
  Bottom 0.813: 12.38,22.7 Q201.B | 12.38,22.7 R201.2 | 12.38,22.7 9.84,22.7 8.57,23.96 C201.+
N$32
  Top 0.813: R202.2 15.34,20.37 Q201.E
N$33
  Top 0.813: Q202.E 12.38,10 11.74,10.63 R203.2
N$34
  Top 0.813: R203.1 11.74,17.61 | 11.74,17.61 R202.1 | 11.74,17.61 R205.2
N$35
  Bottom 0.61: 32.7,17.61 IC201.3 | 30.16,17.61 IC201.14 30.16,14.44 29.52,13.81 28.25,13.81 R211.1
  Bottom 0.813: 30.16,17.61 32.7,17.61 | C206.2 26.35,14.44 28.57,14.44 R211.1
N$36
  Bottom 0.61: IC201.2 31.43,22.06 30.16,23.33
  Bottom 0.813: 30.16,23.33 R216.2
N$37
  Bottom 0.61: IC201.1 30.16,21.42 27.62,23.96 | R212.2 27.62,29.04 R216.3
  Bottom 0.813: 27.62,23.96 R216.3
N$38
  Bottom 0.813: R216.1 36.51,30.31 44.13,30.31 45.4,29.04 45.4,23.96 44.76,23.33 C207.+
N$39
  Bottom 0.61: R212.1 30.79,29.04 30.79,26.5 32.06,25.23 33.33,25.23 37.14,28.41 39.68,28.41 C208.- | R213.2 42.86,28.41 42.73,28.28
  Bottom 0.813: C208.- 42.73,28.28
N$40
  Bottom 0.61: 37.78,20.15 IC201.7 37.78,22.06 39.68,23.96 39.68,24.6 | IC201.6 36.51,22.06 39.05,24.6 39.68,24.6 | 39.68,25.23 C208.+ 39.68,24.6
  Bottom 0.813: R214.1 40.32,23.96 39.68,24.6
N$41
  Bottom 0.813: R215.2 42.22,10 42.86,10.63 C209.- 42.86,13.49 40.32,16.03 R214.2
N$42
  Bottom 0.61: IC201.5 35.24,23.33 38.41,26.5 40.95,26.5 41.59,25.87 42.86,25.87 R213.1
  Bottom 0.813: R213.1 42.86,25.23 42.22,24.6 42.22,16.98 46.67,12.54 C211.+
N$43  (via drill 0.6 pad 1.78)
  Top 0.813: v54.92,63.34 53.02,61.43 53.02,40.48 49.84,37.3 47.3,37.3 44.13,34.12 44.13,25.23 40.95,22.06 40.95,18.88 38.09,16.34 v38.09,12.54
  Bottom 0.61: IC201.9 36.51,13.81 37.14,13.17 37.78,13.17 | 37.78,13.17 IC201.8 | 38.09,13.17 37.78,13.17 | IC501.2 55.56,63.97 v54.92,63.34
  Bottom 0.813: C209.+ 38.09,13.17 v38.09,12.54
N$44
  Bottom 0.61: IC201.10 35.24,13.17 37.14,10.63 37.14,10
  Bottom 0.813: C210.1 37.14,10 R215.1
N$45
  Bottom 0.813: C204.- 21.9,10 22.54,9.36 R209.2
N$47
  Bottom 0.813: Q302.C 19.36,45.55 | 19.36,45.55 R307.1 | 19.36,45.55 19.36,44.92 20,44.28 C304.+
N$48
  Bottom 0.813: 19.36,54.45 20,53.81 24.44,53.81 25.08,53.17 C303.+ | R306.1 19.36,54.45 | 19.36,54.45 19.36,55.08 18.73,55.71 Q301.C
N$50
  Bottom 0.61: IC301.13 31.43,44.28 29.84,42.38 28.57,42.38
  Bottom 0.813: R308.1 24.13,42.38 26.35,42.38 | 26.35,42.38 R311.2 | C306.1 28.57,42.38 26.35,42.38
N$52
  Bottom 0.61: IC301.12 32.7,43.65 30.79,41.43 30.79,40.48 | C305.1 30.79,39.84
  Bottom 0.813: C305.1 30.79,40.48 28.25,40.48 | 28.25,40.48 R310.1 | 28.25,40.48 26.98,40.48 26.35,39.84 R309.1 25.08,39.84
N$53
  Bottom 0.813: C302.+ 12.38,43.02 | 12.38,44.28 R304.2 12.38,43.02 | 12.38,43.02 Q302.B
N$54
  Bottom 0.813: 12.38,53.17 Q301.B | 12.38,53.17 R301.2 | 12.38,53.17 9.84,53.17 8.57,54.45 C301.+
N$55
  Top 0.813: R302.2 15.34,50.85 Q301.E
N$56
  Top 0.813: R303.2 11.74,41.11 12.38,40.48 Q302.E
N$57
  Top 0.813: R303.1 11.74,48.09 | 11.74,48.09 R302.1 | 11.74,48.09 R305.2
N$58
  Bottom 0.406: 28.89,44.92 28.57,44.92 C306.2 | C306.2 28.57,44.28 | 28.31,44.86 28.57,44.86 C306.2
  Bottom 0.61: 30.16,45.55 30.16,48.09 | 32.7,48.09 IC301.3 | 28.31,44.86 30.1,44.86 30.16,44.92 30.16,45.55 | 30.16,45.55 IC301.14
  Bottom 0.813: R311.1 26.35,44.92 28.89,44.92 | 30.16,48.09 32.7,48.09
N$59
  Bottom 0.61: 31.43,50.63 IC301.2 31.43,52.54 30.16,53.81 R316.2
N$60
  Bottom 0.61: 30.16,50.63 IC301.1 30.16,51.91 27.62,54.45 R316.3 27.62,59.52 R312.2
N$61
  Bottom 0.813: R316.1 32.7,58.89 33.97,60.16 44.13,60.16 45.4,58.89 45.4,54.45 44.76,53.81 C307.+
N$62
  Bottom 0.61: R312.1 30.79,59.52 30.79,56.98 32.06,55.71 33.33,55.71 35.87,58.25 39.68,58.25 C308.- | R313.2 42.86,57.62 42.35,58.13
  Bottom 0.813: C308.- 42.35,58.13
N$63
  Bottom 0.61: 37.78,50.63 IC301.7 37.78,52.54 39.68,54.45 | IC301.6 36.51,52.54 38.41,54.45 39.68,54.45 | 39.68,54.45 C308.+
  Bottom 0.813: 39.68,54.45 40.32,53.81 R314.1
N$64
  Bottom 0.813: R314.2 40.32,46.82 42.86,44.28 C309.- 42.86,41.11 42.22,40.48 R315.1
N$65
  Bottom 0.61: IC301.5 35.24,53.17 38.41,56.35 41.59,56.35 42.22,55.71 42.86,55.71
  Bottom 0.813: C311.+ 46.67,43.65 42.22,48.09 42.22,53.81 42.86,54.45 42.86,55.71 R313.1
N$66  (via drill 0.6 pad 1.78)
  Top 0.813: v38.09,43.02 38.09,46.19 40.95,48.73 40.95,52.54 44.13,55.71 44.13,63.34 47.3,66.51 v51.75,66.51
  Bottom 0.61: 37.78,45.55 IC301.8 37.78,43.65 | 36.51,45.55 IC301.9 36.51,44.28 37.14,43.65 37.78,43.65 | 38.09,43.65 37.78,43.65 | v51.75,66.51 IC501.4
  Bottom 0.813: C309.+ 38.09,43.65 v38.09,43.02
N$67
  Bottom 0.61: IC301.10 35.24,43.65 37.14,41.11 37.14,40.48
  Bottom 0.813: C310.1 37.14,40.48 R315.2
N$68
  Bottom 0.813: C301.- 6.03,62.06 JP1.1 6.03,64.61 C102.-
N$69
  Bottom 0.813: C202.- 5.39,12.54 3.49,13.81 3.49,17.61 JP3.1 3.49,20.15 3.49,41.11 C302.-
N$70
  Bottom 0.61: IC501.3 53.65,65.24 51.75,63.34 51.75,60.16 53.02,58.89 R505.1
N$71  (via drill 0.6 pad 1.78)
  Top 0.61: v66.99,55.71 69.53,55.71 | IC503.2 76.51,60.16 76.51,56.35 72.07,56.35 71.43,55.71 69.53,55.71 | 69.53,55.71 R503.2
  Bottom 0.61: R505.2 66.99,58.89 v66.99,55.71
  Bottom 0.813: v66.99,55.71 R504.1
N$72
  Top 0.61: R503.1 69.53,60.16 | 69.53,60.16 R502.2 | 69.53,60.16 IC503.7
N$73
  Top 0.61: IC503.6 71.43,61.43 70.8,62.06 69.53,62.06 | 69.53,62.06 R502.1 | 69.53,62.06 68.26,62.06 67.62,61.43 67.62,59.52 63.18,55.08 R501.2
N$74
  Top 0.61: IC503.1 80.32,58.89 80.96,58.25 80.96,55.71 80.32,55.08 72.7,55.08 70.8,53.17 IC601.6
  Bottom 0.813: R504.2 66.99,51.27 70.16,51.27 70.8,50.63 IC601.6
N$75  (via drill 0.6 pad 1.78)
  Top 0.61: v68.26,70.95 73.34,70.95 | IC502.5 77.15,72.22 75.88,70.95 73.34,70.95 | 73.34,70.95 IC502.11
  Bottom 0.61: IC501.10 67.62,70.32 v68.26,70.95
N$76  (via drill 0.6 pad 1.78)
  Top 0.61: IC502.9 72.07,73.5 71.43,74.13 v66.35,74.13
  Bottom 0.61: IC501.9 65.72,71.59 66.35,72.22 v66.35,74.13
N$77
  Top 0.61: IC502.2 83.5,68.41 84.13,69.05 84.13,72.86 83.5,73.5 IC502.6
N$78  (via drill 0.6 pad 1.78)
  Top 0.61: IC502.12 71.43,69.69 v70.8,69.05 | IC502.8 72.7,74.77 72.7,75.4 73.34,74.77 IC502.8 | IC502.8 73.97,74.77
  Top 0.813: v71.43,76.67 72.7,75.4
  Bottom 0.813: v70.8,69.05 70.8,76.03 v71.43,76.67
N$79
  Bottom 0.61: IC602.10 86.67,15.71 86.04,15.08 82.86,15.08 82.23,15.71 R602.2
N$80
  Bottom 0.61: C602.1 85.4,22.06 IC602.9
N$81
  Top 0.61: 70.8,95.08 IC901.3
  Top 0.813: 65.4,86.19 R901.1 65.4,88.1 | 65.4,88.1 R902.2 | 70.8,95.08 70.16,95.72 58.73,95.72 58.1,95.08 58.1,88.73 58.73,88.1 65.4,88.1
N$82
  Bottom 0.61: IC602.11 87.94,22.06 C602.2
  Bottom 0.813: 87.94,22.06 87.94,23.33 R603.2 R603.1
N$83
  Bottom 0.813: R603.3 84.13,24.6 82.86,24.6 82.23,23.96 R602.1
N$84  (via drill 0.6 pad 1.78)
  Top 0.61: v102.55,13.81 IC603.2
  Bottom 0.61: IC604.2 69.53,36.66 68.89,37.3 62.54,37.3 60.64,35.39 60.64,13.81 65.72,8.09 85.4,8.09 86.67,9.36 | 86.67,9.36 IC602.7 | 86.67,9.36 87.94,8.09 102.55,8.09 v102.55,13.81
N$85  (via drill 0.6 pad 1.78)
  Top 0.61: v75.24,23.96 75.24,20.15 71.43,16.34 64.45,16.34 60,20.79 60,32.22 60.64,32.85 IC601.11
  Bottom 0.61: v75.24,23.96 74.61,24.6 IC604.11
N$86  (via drill 0.6 pad 1.78)
  Top 0.61: v73.34,22.06 73.34,20.79 70.8,18.25 65.08,18.25 61.91,21.42 61.91,31.58 63.18,32.85 IC601.12
  Bottom 0.61: v73.34,22.06 IC604.12
N$87  (via drill 0.6 pad 1.78)
  Top 0.61: v71.43,23.96 71.43,21.42 70.16,20.15 65.72,20.15 63.81,22.06 63.81,30.95 65.72,32.85 IC601.13
  Bottom 0.61: v71.43,23.96 71.43,24.6 72.07,25.87 IC604.13
N$88  (via drill 0.6 pad 1.78)  (1 unrouted)
  Top 0.61: v69.53,22.06 66.35,22.06 65.72,22.7 65.72,30.31 68.26,32.85 IC601.14
  Bottom 0.61: 70.8,28.41 70.8,26.5 69.53,24.6 v69.53,22.06
N$89
  Bottom 0.61: IC604.3 IC601.15
N$90
  Bottom 0.61: IC604.4 72.07,37.94 73.34,39.2 IC601.16
N$91
  Bottom 0.61: IC604.5 73.34,36.66 75.88,39.2 IC601.17
N$92
  Bottom 0.61: IC604.6 74.61,36.03 78.42,39.84 IC601.18
N$93
  Bottom 0.813: R601.1 80.32,44.92 80.96,44.28 IC601.19
N$94
  Bottom 0.61: 75.24,45.55 75.88,46.19 IC601.4
  Bottom 0.813: C607.1 75.24,45.55 | IC601.4 75.88,45.55 76.51,44.92 R601.2
N$95  (via drill 0.6 pad 1.78)
  Top 0.61: v79.05,31.58 87.31,31.58 Q601.C 94.93,34.12 98.1,30.95 R605.1 100.43,27.36 v100.64,27.14 | v112.07,25.87 110.8,25.87 110.17,25.23 IC603.9
  Bottom 0.61: IC604.1 68.26,32.22 68.89,31.58 v79.05,31.58
  Bottom 0.813: v100.64,27.14 101.91,25.87 v112.07,25.87
N$96
  Top 0.61: R604.2 88.58,52.54 93.02,48.09 93.02,38.57 91.12,36.66 Q601.B
N$97  (via drill 0.6 pad 1.78)  (1 unrouted)
  Top 0.61: R604.1 v88.58,62.06
  Bottom 0.61: v88.58,62.06 89.85,60.8 96.2,60.8
N$98
  Bottom 0.61: IC606.12 87.94,59.52 86.04,57.62 86.04,54.45 84.77,53.17 74.61,53.17 73.34,51.91 IC601.5
N$99  (via drill 0.6 pad 1.78)  (1 unrouted)
  Top 0.61: IC701.11 102.55,78.58 103.18,77.94 103.18,74.77 v102.55,74.13
  Bottom 0.61: 100.01,74.13 99.37,74.13 | 100.01,74.13 v102.55,74.13 | 101.28,62.06 102.55,62.06 102.55,63.34 101.28,64.61 96.2,64.61 95.56,65.24 95.56,72.86 96.83,74.13 100.01,74.13
N$100  (via drill 0.6 pad 1.78)
  Top 0.61: IC605.11 108.9,48.09 108.9,52.54 110.17,53.81 110.17,57.62 108.26,59.52 100.64,59.52 | IC603.10 108.9,27.14 110.17,28.41 113.34,28.41 114.61,29.68 112.71,29.68 TP602.1
  Top 0.813: 114.61,29.68 114.61,45.55 113.34,46.82 110.17,46.82 108.9,48.09 | v93.02,57.62 98.74,57.62 100.64,59.52 R606.1
  Bottom 0.61: IC606.11 93.66,58.25 v93.02,57.62
N$101
  Top 0.813: R606.2 Q602.B
N$102  (via drill 0.6 pad 1.78)  (1 unrouted)
  Top 0.61: v67.62,23.96 67.62,25.23 68.89,26.5 76.51,26.5 77.78,25.23 79.05,25.23 82.23,22.06 106.99,22.06 107.63,22.7 IC603.11 107.63,27.77 108.9,29.04 108.9,30.95 108.26,31.58 106.99,31.58 106.36,32.22 106.36,36.03 106.36,37.3 105.09,38.57 104.45,38.57 101.91,41.11 101.91,44.92 103.18,46.19 103.18,50 108.9,54.76 108.9,56.98 108.26,57.62 v104.77,57.62
  Bottom 0.61: IC604.15 69.53,27.14 67.62,24.6 v67.62,23.96 | IC606.5 104.13,56.98 v104.77,57.62
N$103  (via drill 0.6 pad 1.78)
  Top 0.61: v79.05,28.41 79.69,28.41 81.59,30.31 v95.56,30.31 | v101.28,38.57 100.64,39.2 100.64,55.71 v106.99,55.71
  Bottom 0.61: IC604.9 78.95,28.51 v79.05,28.41 | IC606.6 103.82,55.71 104.45,55.08 106.36,55.08 v106.99,55.71
  Bottom 0.813: v95.56,30.31 101.28,36.66 v101.28,38.57
N$104  (via drill 0.6 pad 1.78)
  Top 0.61: IC502.3 81.59,69.69 82.23,70.32 v82.23,71.59 | IC603.15 102.55,32.22 98.1,36.66 98.1,48.73 96.83,50 94.93,50 93.02,51.91 93.02,54.45 90.48,56.98 90.48,63.34 88.58,65.24 v88.58,69.05
  Bottom 0.61: 101.91,60.8 IC606.2 100.01,60.8 98.74,61.43 98.74,62.06 97.47,63.34 95.56,63.34 94.29,64.61 94.29,67.14 92.39,69.05 v88.58,69.05 84.13,69.05 82.23,70.95 v82.23,71.59
N$105
  Bottom 0.61: IC606.4 101.91,58.25 101.81,58.36 IC606.3
N$106  (1 unrouted)
  Top 0.61: IC603.13 105.09,36.03
N$107  (via drill 0.6 pad 1.78)
  Top 0.61: v91.12,53.17 91.12,51.91 94.29,48.73 96.2,48.73 96.83,48.09 96.83,36.03 101.28,31.58 101.28,30.31 v100.64,29.68 | IC603.12 106.36,29.04 v106.99,29.68
  Bottom 0.61: IC606.9 93.66,55.71 v91.12,53.17
  Bottom 0.813: v106.99,29.68 v100.64,29.68
N$108  (via drill 0.6 pad 1.78)
  Top 0.61: IC603.14 103.82,32.85 99.37,37.3 99.37,52.54 v95.56,52.54
  Bottom 0.61: IC606.8 95.56,54.45 v95.56,52.54
N$109
  Top 0.61: IC605.3 108.8,35.5 108.9,35.39 IC605.4 110.07,35.5 110.17,35.39 IC605.5
N$110  (1 unrouted)
  Top 0.61: IC605.12 107.63,39.2 108.26,38.57 110.17,38.57 111.44,37.3 111.44,36.03
N$111  (via drill 0.6 pad 1.78)
  Top 0.61: IC605.13 106.36,50 v106.99,50.63
  Bottom 0.61: IC606.10 98.1,56.98 98.74,56.35 98.74,53.17 99.37,52.54 105.72,52.54 106.99,51.27 v106.99,50.63
N$112
  Bottom 0.61: R607.1 82.23,45.55 80.96,46.82 IC601.2 80.96,50 82.23,51.27 89.85,51.27 92.39,48.73 108.26,48.73 110.17,50.63 110.17,58.57 107.63,61.11 106.36,61.11 105.72,61.75 105.72,64.61 103.18,67.14 Q602.C 103.18,68.41
  Bottom 0.813: IC601.2 IC601.3
N$113
  Top 0.61: IC701.14 105.72,82.39 | 108.26,80.48 X701.2
  Top 0.813: 105.72,82.39 106.36,82.39 108.26,80.48
N$114
  Top 0.61: IC701.5 89.85,79.84 89.21,79.21 89.21,76.67 88.58,76.03 87.94,76.03 87.31,76.67 C702.-
N$115
  Top 0.61: IC701.3 87.94,82.39 87.31,83.02 C701.-
N$116
  Top 0.61: C702.+ 87.31,80.48 87.94,81.11 IC701.4
N$117
  Top 0.61: IC701.1 89.85,84.92 89.21,85.56 89.21,88.1 87.94,88.1 87.31,87.47 C701.+
N$118
  Top 0.61: IC701.6 93.66,78.58 94.29,77.94 94.29,72.86 C703.-
N$119
  Top 0.61: C704.+ 91.75,88.1 91.12,87.47 91.12,86.83 91.75,86.19 94.29,86.19 94.93,85.56 94.93,84.29 94.29,83.66 IC701.2
N$120
  Top 0.61: IC701.13 104.45,81.11 106.36,79.21 | 108.26,75.4 X701.4
  Top 0.813: 108.26,75.4 106.99,75.4 106.36,76.03 106.36,79.21
N$128
  Top 0.61: IC601.9 R501.1
N$132  (via drill 0.6 pad 1.78)
  other vias: 67.62,88.1
V+  (via drill 0.6 pad 1.78)  (1 unrouted)
  Top 0.61: IC901.7 72.07,83.02 71.43,82.39 | IC503.8 72.7,58.89 v72.07,58.25 | 73.34,67.14 IC502.14 76.51,67.14 | 76.51,67.14 IC502.1 | IC502.13 73.34,68.41 73.34,67.14 | IC502.4 77.78,70.95 76.51,69.69 76.51,67.14 | 75.24,72.22 IC502.10 | 73.34,67.14 v68.26,67.14 67.62,67.14 66.35,68.41 66.35,71.59 67.62,72.86 70.8,72.86 71.43,72.22 75.24,72.22 | v64.13,82.39 74.61,82.39 | C501.1 76.51,73.5 75.24,72.22 | IC603.7 107.73,18.35 107.63,18.25 IC603.6 106.46,18.35 106.36,18.25 | 105.09,18.25 105.19,18.35 IC603.5 106.36,18.25 | IC603.16 101.28,24.6 98.1,24.6 | 104.45,43.02 105.09,42.38 IC605.14 | 98.1,24.6 R605.2 | 98.1,24.6 96.2,24.6 v95.56,25.23 | v95.56,20.15 95.56,16.98 96.83,15.71 100.01,15.71 101.28,16.98 IC603.1 101.28,20.15 101.91,20.79 105.72,20.79 106.36,20.15 106.36,18.25 | C603.2 105.72,15.71 105.09,16.34 105.09,18.25 | 105.09,18.25 IC603.4 | 101.28,84.92 101.91,84.92 | 78.73,83.97 79.05,83.66 | 96.83,88.1 96.83,86.19 98.1,84.92 101.28,84.92 | 101.28,84.92 IC701.16
  Top 0.813: v32.7,82.39 32.06,81.75 | v32.7,82.39 35.24,84.92 35.24,89.37 35.87,90 | v33.33,53.17 30.79,50.63 30.79,41.74 35.24,37.3 35.24,24.6 v33.33,22.7 32.7,22.06 28.25,22.06 26.98,23.33 22.54,23.33 21.27,22.06 v21.27,18.88 | v33.33,53.17 35.24,55.08 35.24,65.88 30.16,70.95 30.16,79.84 v32.7,82.39 | v21.27,77.94 21.27,89.37 21.9,90 35.87,90 | 35.87,90 51.75,90 52.38,89.37 v52.38,85.56 | v64.13,82.39 64.77,82.39 | 64.77,82.39 65.4,83.02 R901.2 65.4,84.92 | 64.77,82.39 71.43,82.39 74.61,82.39 77.15,82.39 78.73,83.97 79.05,84.29 | 79.05,84.29 C904.1 | 79.05,84.29 IC902.1 78.84,87.25 C903.2 | IC601.20 83.5,42.38 86.67,45.55 C601.+ 87.31,45.55 86.04,46.82 86.04,57.62 84.13,59.52 84.13,65.88 86.04,67.78 86.04,73.5 | v104.45,44.28 104.45,43.02 | C606.2 93.02,68.41 91.75,69.69 | 79.05,83.66 82.14,81.01 | 82.14,81.01 83.5,79.84 83.5,76.03 86.04,73.5 | v21.27,49.37 21.27,52.54 22.54,53.81 27.62,53.81 28.89,52.54 32.7,52.54 v33.33,53.17 | 82.14,81.01 82.14,81.03 84.13,83.02 84.13,88.1 86.67,90.64 95.56,90.64 96.83,89.37 96.83,88.1 | 91.75,69.69 v91.75,65.24 | 91.75,69.69 89.85,71.59 87.94,71.59 86.04,73.5 | 96.83,88.1 C705.+ | 96.83,88.1 C704.-
  Bottom 0.61: 33.97,50.63 IC301.4 33.97,52.54 v33.33,53.17 | IC101.4 33.33,81.75 v32.7,82.39 | IC201.4 33.97,22.06 v33.33,22.7 | C601.+ R607.2 | v72.07,58.25 71.43,58.25 66.99,62.7 | 66.99,62.7 IC501.16 | v68.26,67.14 68.26,63.97 66.99,62.7 | IC604.10 75.88,27.14 77.15,25.87 77.15,21.42 75.88,20.15 67.62,20.15 65.72,22.06 65.72,25.23 68.26,27.77 IC604.16 | 81.59,35.39 C604.2 | v104.45,44.28 C605.2 | v95.56,20.15 94.29,18.88 IC602.16 | 96.2,62.06 93.02,62.06 91.75,63.34 v91.75,65.24
  Bottom 0.813: 19.36,48.09 R307.2 19.36,49.37 | 19.36,49.37 R306.2 19.36,50 | 19.36,16.98 R207.2 19.36,18.88 | 18.73,76.03 R107.2 18.73,77.94 | 19.36,18.88 R206.2 | v21.27,49.37 19.36,49.37 | 19.36,18.88 v21.27,18.88 | 18.73,77.94 R106.2 | v21.27,77.94 18.73,77.94 | v52.38,85.56 JP901.4 54.92,84.92 57.46,82.39 C901.+ v64.13,82.39 68.89,82.39 70.16,81.11 73.97,81.11 75.88,79.21 75.88,68.41 74.61,67.14 v68.26,67.14 | IC601.20 83.5,37.94 82.23,36.03 | 82.23,36.03 82.23,30.31 | 77.15,25.87 80.32,25.87 82.23,27.77 82.23,30.31 | 82.23,36.03 81.59,35.39 | C601.+ 90.48,44.28 v104.45,44.28 | 82.23,30.31 83.5,29.04 93.02,29.04 95.56,26.5 v95.56,25.23 v95.56,20.15
V-  (via drill 0.6 pad 1.78)  (1 unrouted)
  Top 0.61: IC901.4 69.53,93.18 68.89,93.81 64.77,93.81 | IC503.4 80.32,62.7 80.96,63.34 80.96,65.24 80.32,65.88 70.16,65.88 69.53,65.24 63.18,65.24 61.91,66.51 v61.91,76.03
  Top 0.813: R205.1 18.09,17.61 18.73,18.25 18.73,48.73 | 18.73,48.73 18.73,76.67 | 18.73,76.67 R105.1 | R305.1 18.09,48.09 18.73,48.73 | v33.97,11.27 33.97,17.61 37.14,20.15 37.14,38.57 v33.97,41.74 33.97,48.09 37.14,50.63 37.14,67.14 v33.33,70.95 33.33,77.3 35.87,79.84 40.32,79.84 43.49,83.02 v46.67,83.02 51.75,83.02 58.73,76.03 v61.91,76.03 | 18.73,76.67 18.73,90.64 21.27,93.18 v46.67,93.18 | R902.1 65.4,93.18 64.77,93.81 v64.13,93.81 | C903.1 75.88,89.37 IC902.2
  Bottom 0.61: v33.97,11.27 IC201.11 | v33.97,41.74 IC301.11 | v33.33,70.95 IC101.11 | 58.1,62.7 IC501.1 61.91,62.7 61.91,70.32 | 61.91,70.32 58.1,70.32 | v61.91,76.03 61.91,70.32
  Bottom 0.813: v46.67,83.02 v46.67,93.18 JP901.1 58.73,93.18 59.37,93.81 C902.- v64.13,93.81 79.05,93.81 80.32,92.55 IC902.2
(copper drawn outside any net)
  shapes: Bottom area x31, Top area x8

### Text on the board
Top: - | + | yellow | GND | red | green | ECG AMPLIFIER | Rev. 1.2b | FHNW | DV / OE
